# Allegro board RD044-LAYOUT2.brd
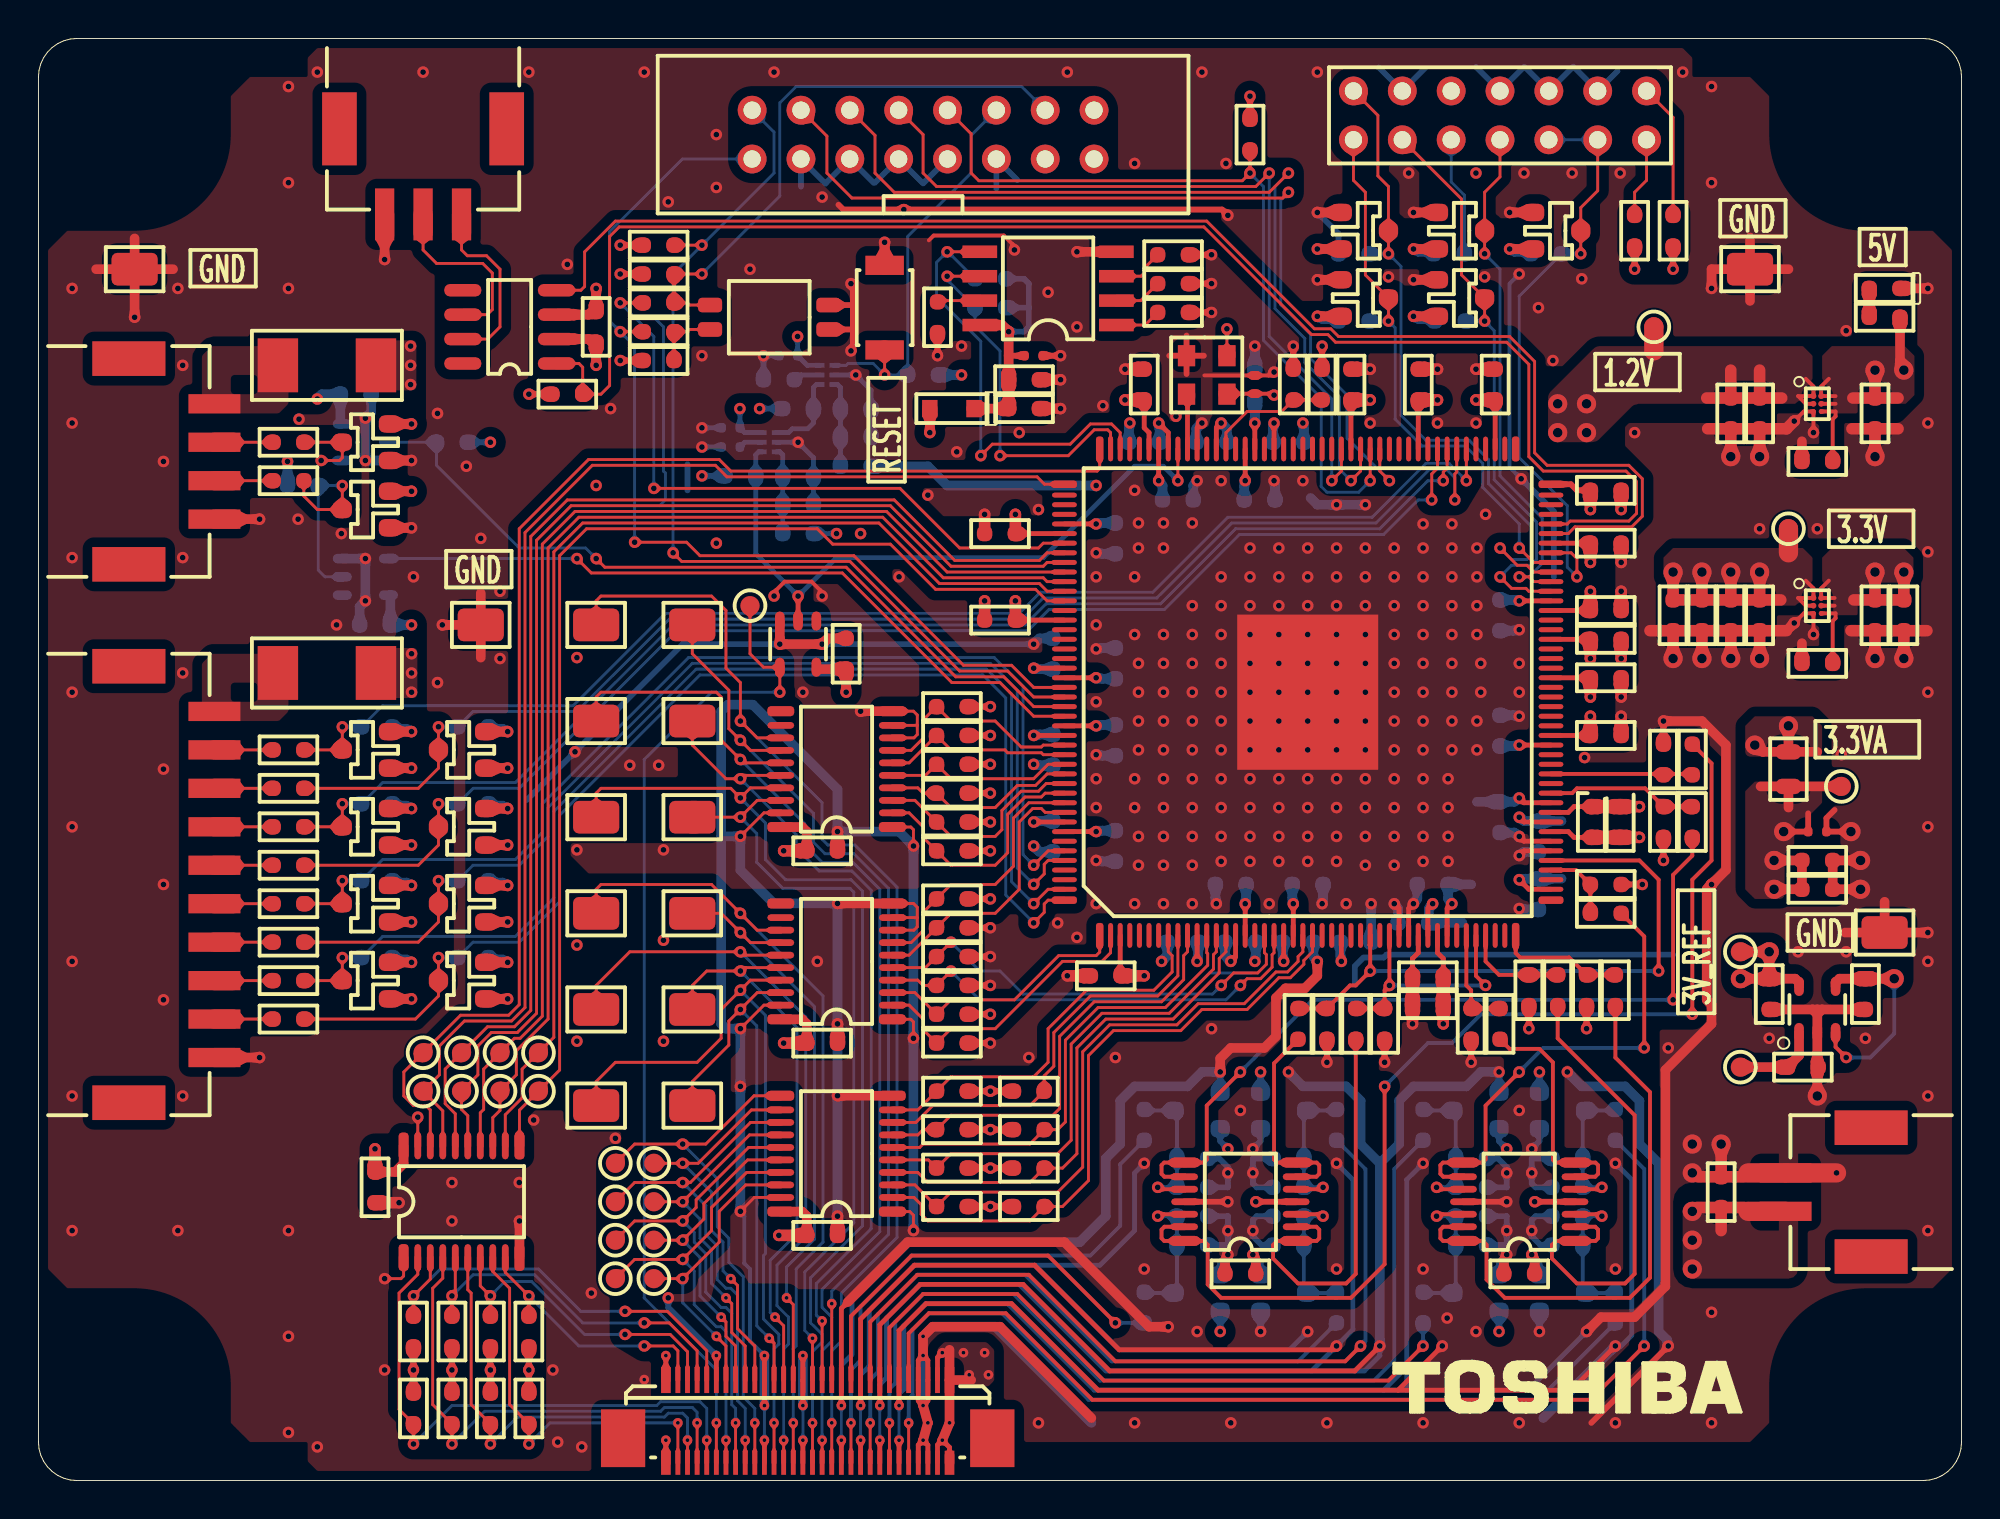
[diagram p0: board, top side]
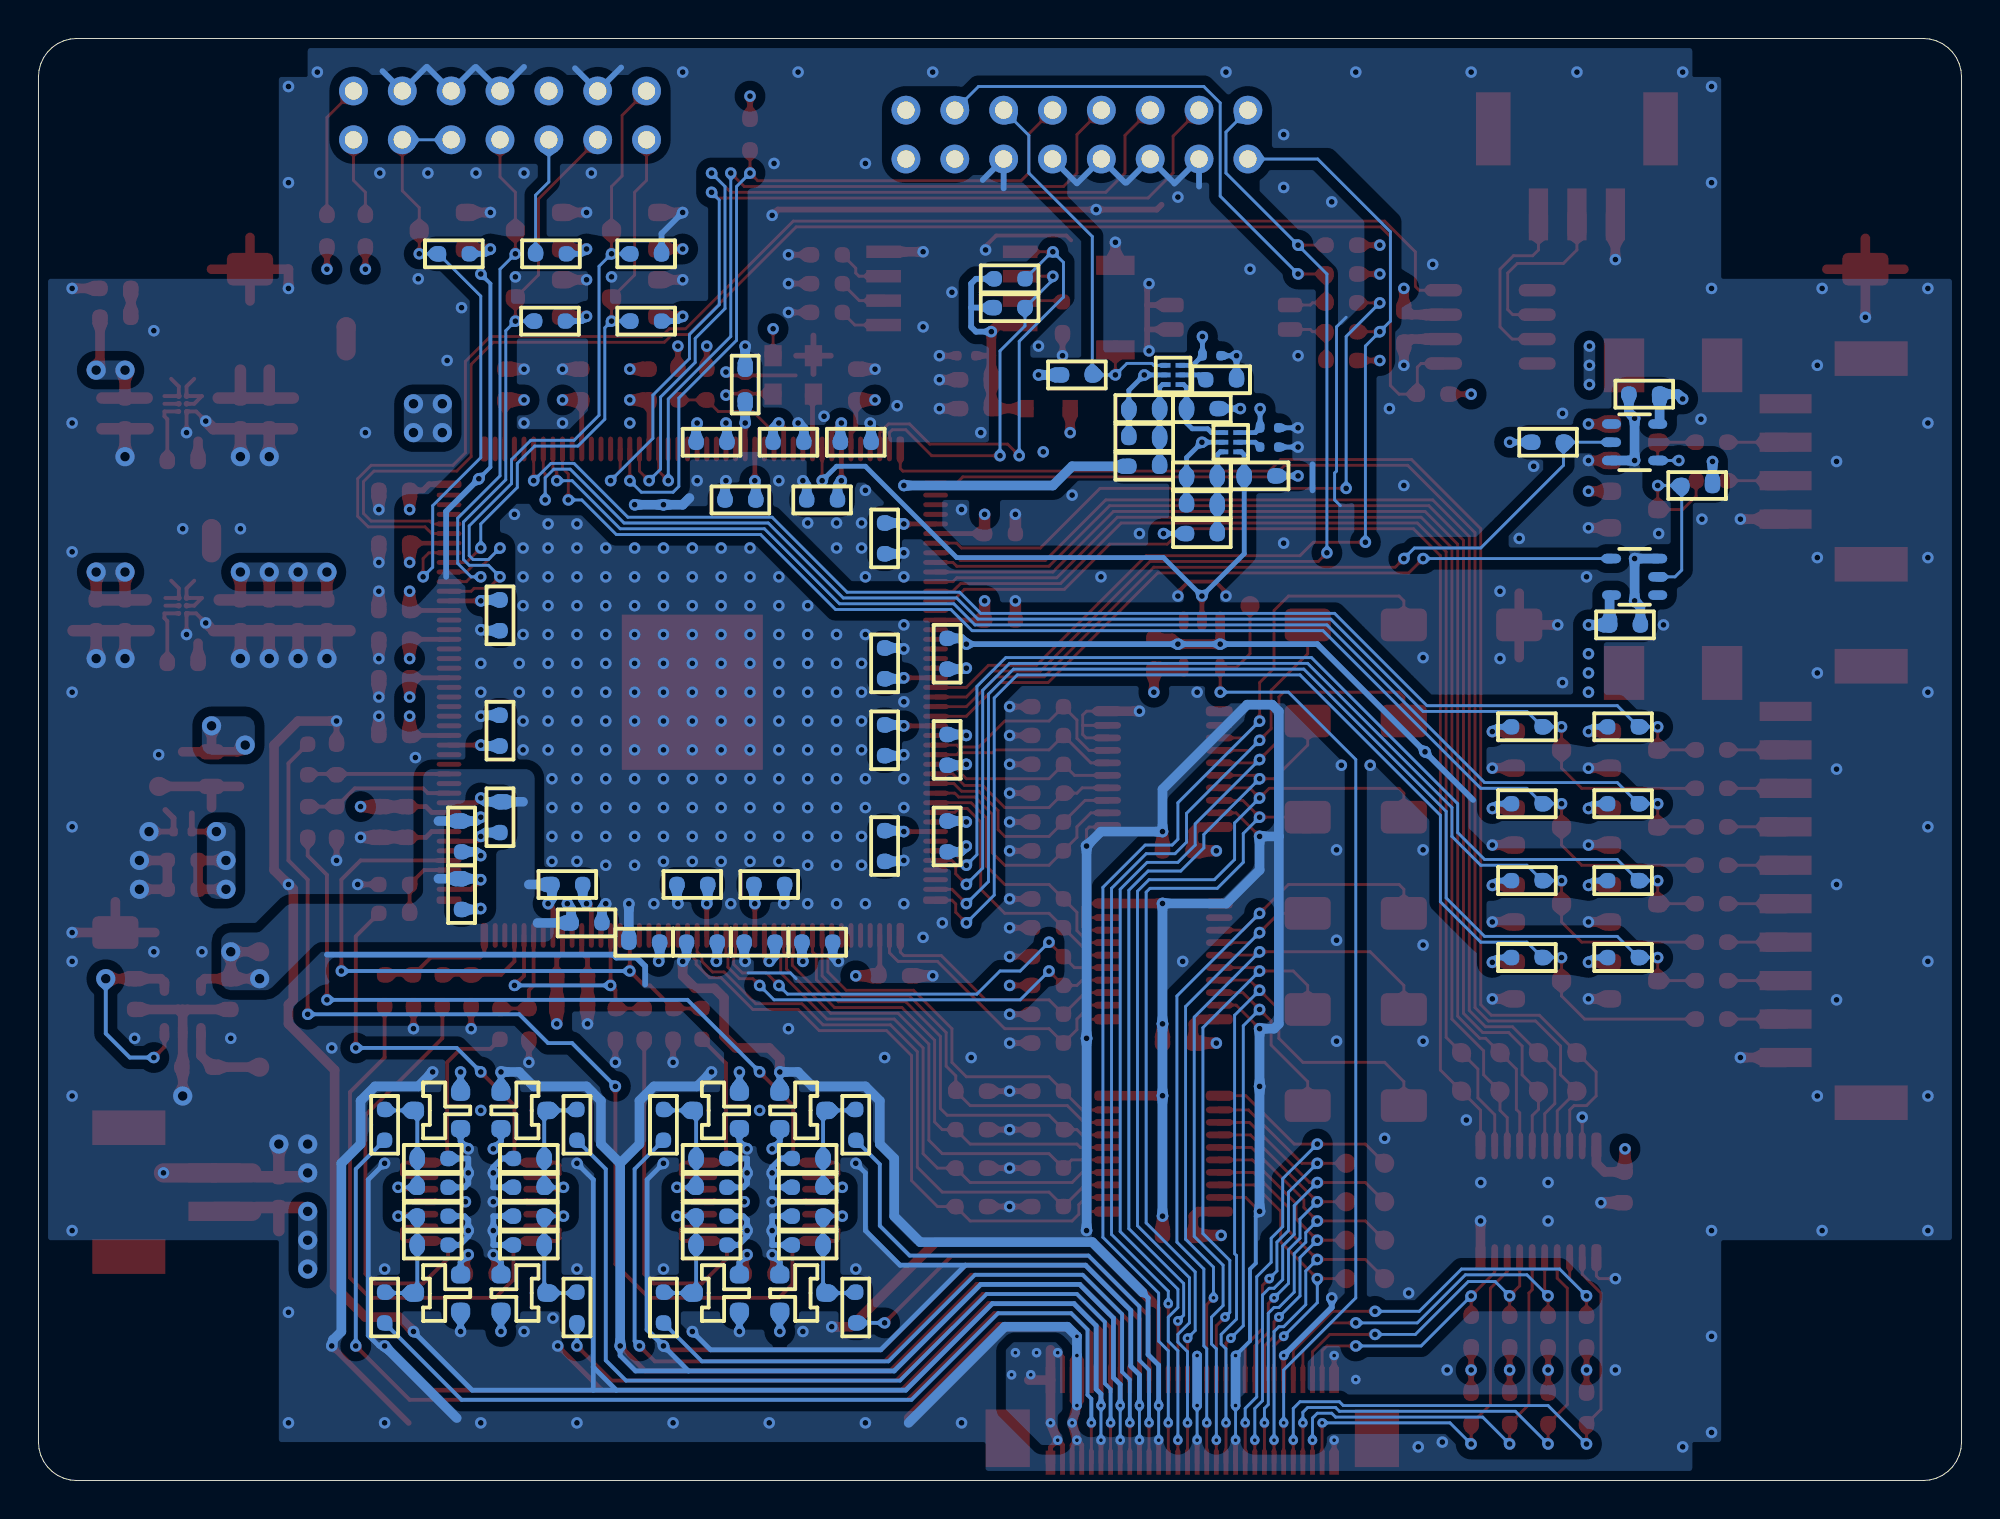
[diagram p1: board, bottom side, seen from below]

Outline 100 x 75 mm; copper layers: TOP, CONDUCTIVE2, CONDUCTIVE3, BOTTOM. Coordinates in mm from the lower left corner of the outline.
Outline path: 0,73 0.03,73.35 0.12,73.68 0.27,74 0.47,74.29 0.71,74.53 1,74.73 1.32,74.88 1.65,74.97 2,75 98,75 98.35,74.97 98.68,74.88 99,74.73 99.29,74.53 99.53,74.29 99.73,74 99.88,73.68 99.97,73.35 100,73 100,2 99.97,1.65 99.88,1.32 99.73,1 99.53,0.71 99.29,0.47 99,0.27 98.68,0.12 98.35,0.03 98,0 2,0 1.65,0.03 1.32,0.12 1,0.27 0.71,0.47 0.47,0.71 0.27,1 0.12,1.32 0.03,1.65 0,2 0,73

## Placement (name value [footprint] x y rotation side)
C1  -  [C_1005]  36 54.75 180 bottom
C2  -  [C_1608]  42.5 55.75 0 bottom
C3  -  [C_1608]  38.5 57.25 180 bottom
C4  -  [C_1608]  39.5 52.25 0 bottom
C5  -  [C_1005]  36 53.75 180 bottom
C6  -  [C_1005]  63.25 57 90 top
C7  -  [C_1005]  39 58.5 180 bottom
C8  -  [C_1608]  72.25 26.25 180 top
C9  -  [C_1608]  72.25 24.75 180 top
C10  -  [C_1608]  71.5 29 180 bottom
C11  -  [C_1608]  72.5 31 180 bottom
C12  -  [C_1608]  80.75 34.25 270 top
C13  -  [C_1608]  82.25 34.25 270 top
C14  -  [C_1608]  78 30.5 270 bottom
C15  -  [C_1608]  78 33.5 270 bottom
C16  -  [C_1608]  76 34.5 270 bottom
C17  -  [C_1005]  51.75 58.5 0 top
C18  -  [C_1608]  51.25 57.25 0 top
C19  -  [C_1608]  51.25 55.75 0 top
C20  -  [C_1608]  62 31 180 bottom
C21  -  [C_1608]  66 31 0 bottom
C22  -  [C_1608]  76 39 90 bottom
C23  -  [C_1608]  76 45 270 bottom
C24  -  [C_1608]  63.5 51 0 bottom
C25  -  [C_1608]  59.25 51 0 bottom
C26  -  [C_1608]  56 49 270 bottom
C27  -  [C_1608]  56 42.5 90 bottom
C28  -  [C_1608]  56 38.5 270 bottom
C29  -  [C_1608]  56 33 270 bottom
C30  -  [C_1608]  55.5 26.25 180 top
C31  -  [C_1608]  59.5 28 180 bottom
C32  -  [C_1608]  62.5 28 0 bottom
C33  -  [C_1608]  65.5 28 0 bottom
C34  -  [C_1608]  68.5 28 0 bottom
C35  -  [C_1608]  81.5 38.75 0 top
C36  -  [C_1608]  81.5 41.75 0 top
C37  -  [C_1608]  81.5 43.75 0 top
C38  -  [C_1608]  81.5 45.25 0 top
C39  -  [C_1608]  81.5 48.75 0 top
C40  -  [C_1608]  81.5 51.5 0 top
C41  -  [C_1608]  75.75 57 90 top
C42  -  [C_1608]  71.75 57 90 top
C43  -  [C_1608]  68.25 57 90 top
C44  -  [C_1608]  65 54 0 bottom
C45  -  [C_1608]  63.25 57 90 bottom
C46  -  [C_1608]  61 54 180 bottom
C47  -  [C_1608]  57.5 54 180 bottom
C48  -  [C_1608]  57.5 57 90 top
C49  -  [C_1608]  50 49.25 180 top
C50  -  [C_1608]  50 44.75 180 top
C51  -  [C_1608]  52.75 43 90 bottom
C52  -  [C_1608]  52.75 38 270 bottom
C53  -  [C_1608]  52.75 33.5 270 bottom
C54  -  [C_1608]  40.75 32.75 0 top
C55  -  [C_1608]  40.75 22.75 0 top
C56  -  [C_1608]  40.75 12.75 0 top
C57  -  [C_1608]  42 43 90 top
C58  -  [C_1608]  79.5 13.75 180 bottom
C59  -  [C_1608]  74.5 13.75 0 bottom
C60  -  [C_1608]  77 10.75 180 top
C61  -  [C_1608]  79.5 15.25 180 bottom
C62  -  [C_1608]  74.5 15.25 0 bottom
C63  -  [C_1608]  77.5 25.5 270 top
C64  -  [C_1608]  81.5 31 0 top
C65  -  [C_1608]  74.5 23.75 270 top
C66  -  [C_1608]  80.5 25.5 270 top
C67  -  [C_1608]  65 13.75 180 bottom
C68  -  [C_1608]  60 13.75 0 bottom
C69  -  [C_1608]  62.5 10.75 180 top
C70  -  [C_1608]  65 15.25 180 bottom
C71  -  [C_1608]  60 15.25 0 bottom
C72  -  [C_1608]  70 23.75 270 top
C73  -  [C_1608]  84.5 34.25 270 top
C74  -  [C_1608]  67 23.75 270 top
C75  -  [C_1608]  84.5 37.5 90 top
C76  -  [C_1608]  17.5 15.25 270 top
C77  -  [C_1608]  29 60 270 top
C78  -  [C_1608]  16.5 56.5 0 bottom
C79  -  [C_1608]  87.5 15 90 top
C80  -  [C_1608]  17.5 44.5 180 bottom
C81  -  [C_1608]  95.5 45 270 top
C82  -  [C_1608]  97 45 270 top
C83  -  [C_1005]  92.5 33.75 0 top
C84  -  [C_1608]  92.5 30.75 0 top
C85  -  [C_1608]  92.5 42.5 180 top
C86  -  [C_1608]  89.5 45 270 top
C87  -  [C_1608]  88 45 270 top
C88  -  [C_1608]  86.5 45 270 top
C89  -  [C_1608]  85 45 270 top
C90  -  [C_1608]  92.5 32.25 0 top
C91  -  [C_1608]  90 25.3 270 top
C92  -  [C_1608]  95.5 55.5 270 top
C93  -  [C_1608]  89.5 55.5 270 top
C94  -  [C_1608]  88 55.5 270 top
C95  -  [C_1608]  91.75 21.5 0 top
C96  -  [C_1608]  92.5 53 180 top
C97  -  [C_1608]  95 25.3 270 top
CN1  -  [CN_XG8W_1431]  76 71 0 top
CN2  -  [CN_XG4C_1631]  46 70 0 top
CN3  -  [CN_WR_60P_HF_HD_A1E]  40 3.05 0 top
CN4  -  [CN_SM03B_PASS_TBT]  20 70.85 0 top
CN5  -  [CN_SM02B_PASS_TBT]  95.85 15 270 top
CN6  -  [CN_SM04B_PASS_TBT]  4.15 53 90 top
CN7  -  [CN_SM10B_PASS_TBT]  4.15 31 90 top
D1  -  [D_SC_59_TO_236MOD_SO_1]  69 61.5 0 top
D2  -  [D_SC_59_TO_236MOD_SO_1]  69 65 0 top
D3  -  [D_SC_59_TO_236MOD_SO_1]  74 61.5 0 top
D4  -  [D_SC_59_TO_236MOD_SO_1]  74 65 0 top
D5  -  [D_SC_59_TO_236MOD_SO_1]  79 65 0 top
D6  -  [D_1_1E1A_USC_AK]  47.5 55.75 0 top
D7  -  [D_SC_59_TO_236MOD_SO_1]  79.25 9.75 0 bottom
D8  -  [D_SC_59_TO_236MOD_SO_1]  74.75 9.75 180 bottom
D9  -  [D_SC_59_TO_236MOD_SO_1]  79.25 19.25 0 bottom
D10  -  [D_SC_59_TO_236MOD_SO_1]  74.75 19.25 180 bottom
D11  -  [D_SC_59_TO_236MOD_SO_1]  64.75 9.75 0 bottom
D12  -  [D_SC_59_TO_236MOD_SO_1]  60.25 9.75 180 bottom
D13  -  [D_SC_59_TO_236MOD_SO_1]  64.75 19.25 0 bottom
D14  -  [D_SC_59_TO_236MOD_SO_1]  60.25 19.25 180 bottom
D15  -  [D_SC_59_TO_236MOD_SO_1]  17 54 180 top
D16  -  [D_SC_59_TO_236MOD_SO_1]  17 50.5 180 top
D17  -  [D_SC_59_TO_236MOD_SO_1]  17 38 180 top
D18  -  [D_SC_59_TO_236MOD_SO_1]  22 38 180 top
D19  -  [D_SC_59_TO_236MOD_SO_1]  17 34 180 top
D20  -  [D_SC_59_TO_236MOD_SO_1]  22 34 180 top
D21  -  [D_SC_59_TO_236MOD_SO_1]  17 30 180 top
D22  -  [D_SC_59_TO_236MOD_SO_1]  22 30 180 top
D23  -  [D_SC_59_TO_236MOD_SO_1]  17 26 180 top
D24  -  [D_SC_59_TO_236MOD_SO_1]  22 26 180 top
FU1  -  [F_CCF1N]  15 58 0 top
FU2  -  [F_CCF1N]  15 42 0 top
IC1  -  [IC_SON6_0_5_DRY_R_PU_1]  41 57.5 270 bottom
IC2  -  [IC_SON6_0_5_DRY_R_PU_1]  38 54 270 bottom
IC3  -  [IC_QFP176_0_5_S_PQFP_1]  66 41 0 top
IC4  -  [IC_SOP8_1_27_SM]  52.5 62 90 top
IC5  -  [IC_SOP20_0_65_TSSOP2_1]  41.5 37 90 top
IC6  -  [IC_SOP20_0_65_TSSOP2_1]  41.5 27 90 top
IC7  -  [IC_SOP20_0_65_TSSOP2_1]  41.5 17 90 top
IC8  -  [IC_SSOP5_P_0_95_TOSH_1]  39.5 43.5 90 top
IC9  -  [IC_SOP14_0_65_PW]  77 14.5 90 top
IC10  -  [IC_SOP14_0_65_PW]  62.5 14.5 90 top
IC11  -  [IC_SOP20_0_65_TSSOP2_1]  22 14.5 0 top
IC12  -  [IC_SOP8_1_27_D]  24.5 60 90 top
IC13  -  [IC_SSOP5_P_0_95_TOSH_1]  17 54 0 bottom
IC14  -  [IC_SSOP5_P_0_95_TOSH_1]  17 47 180 bottom
IC15  -  [IC_SOP5_0_95_DDC]  92.5 24.5 270 top
L1  -  [L_2012]  91 37 90 top
LED1  -  [LED_1608_AK]  96 62 0 top
NOREF  -  []  95 70 0 top
NOREF#2  -  []  5 70 0 top
NOREF#3  -  []  5 5 0 top
NOREF#4  -  []  70.5 3.5 0 top
NOREF#5  -  []  95 5 0 top
PAD1  -  [TP_PAD1_0]  32 10.5 0 top
PAD2  -  [TP_PAD1_0]  30 10.5 0 top
PAD3  -  [TP_PAD1_0]  32 12.5 0 top
PAD4  -  [TP_PAD1_0]  30 12.5 0 top
PAD5  -  [TP_PAD1_0]  32 14.5 0 top
PAD6  -  [TP_PAD1_0]  30 14.5 0 top
PAD7  -  [TP_PAD1_0]  32 16.5 0 top
PAD8  -  [TP_PAD1_0]  30 16.5 0 top
PAD9  -  [TP_PAD1_0]  37 45.5 0 top
PAD10  -  [TP_PAD1_0]  20 22.25 0 top
PAD11  -  [TP_PAD1_0]  20 20.25 0 top
PAD12  -  [TP_PAD1_0]  22 22.25 0 top
PAD13  -  [TP_PAD1_0]  22 20.25 0 top
PAD14  -  [TP_PAD1_0]  24 22.25 0 top
PAD15  -  [TP_PAD1_0]  24 20.25 0 top
PAD16  -  [TP_PAD1_0]  26 22.25 0 top
PAD17  -  [TP_PAD1_0]  26 20.25 0 top
PAD18  -  [TP_PAD1_0]  91 49.5 0 top
PAD19  -  [TP_PAD1_0]  93.75 36.1 0 top
PAD20  -  [TP_PAD1_0]  88.5 27.5 0 top
PAD21  -  [TP_PAD1_0]  84 60 0 top
PAD22  -  [TP_PAD1_0]  88.5 21.5 0 top
PS1  -  [BGA_6_0_4_WCSP6F]  92.5 45.5 0 top
PS2  -  [BGA_6_0_4_WCSP6F]  92.5 56 0 top
R1  -  [R_1608]  46 57.5 180 bottom
R2  -  [R_1608]  39.5 49.25 180 bottom
R3  -  [R_1608]  42.5 54.25 0 bottom
R4  -  [R_1608]  39.5 50.75 0 bottom
R5  -  [R_1608]  39.5 55.75 0 bottom
R6  -  [R_1608]  42.5 52.75 180 bottom
R7  -  [R_1608]  36.5 52.25 0 bottom
R8  -  [R_1608]  68.4 60.3 0 bottom
R9  -  [R_1608]  73.4 60.3 0 bottom
R10  -  [R_1608]  78.4 63.8 0 bottom
R11  -  [R_1608]  73.35 63.8 0 bottom
R12  -  [R_1608]  83 65 90 top
R13  -  [R_1608]  85 65 90 top
R14  -  [R_1608]  68.4 63.8 180 bottom
R15  -  [R_1608]  32.25 64.25 180 top
R16  -  [R_1608]  63 70 90 top
R17  -  [R_1608]  32.25 62.75 0 top
R18  -  [R_1608]  66.75 57 270 top
R19  -  [R_1608]  65.25 57 270 top
R20  -  [R_1608]  49.5 61 0 bottom
R21  -  [R_1608]  49.5 62.5 0 bottom
R22  -  [R_1608]  59 60.75 180 top
R23  -  [R_1608]  59 62.25 180 top
R24  -  [R_1608]  59 63.75 180 top
R25  -  [R_1608]  46.75 60.5 90 top
R26  -  [R_1608]  32.25 58.25 0 top
R28  -  [R_1608]  32.25 59.75 0 top
R29  -  [R_1608]  32.25 61.25 0 top
R30  -  [R_1608]  47.5 32.75 0 top
R31  -  [R_1608]  47.5 34.25 0 top
R32  -  [R_1608]  47.5 35.75 0 top
R33  -  [R_1608]  47.5 37.25 0 top
R34  -  [R_1608]  47.5 38.75 0 top
R35  -  [R_1608]  47.5 40.25 0 top
R36  -  [R_1608]  47.5 22.75 0 top
R37  -  [R_1608]  47.5 24.25 0 top
R38  -  [R_1608]  47.5 25.75 0 top
R39  -  [R_1608]  47.5 27.25 0 top
R40  -  [R_1608]  47.5 28.75 0 top
R41  -  [R_1608]  47.5 30.25 0 top
R42  -  [R_1608]  51.5 14.25 180 top
R43  -  [R_1608]  47.5 14.25 0 top
R44  -  [R_1608]  51.5 16.25 180 top
R45  -  [R_1608]  47.5 16.25 0 top
R46  -  [R_1608]  51.5 18.25 180 top
R47  -  [R_1608]  47.5 18.25 0 top
R48  -  [R_1608]  51.5 20.25 180 top
R49  -  [R_1608]  47.5 20.25 0 top
R50  -  [R_1608]  82 9 270 bottom
R51  -  [R_1608]  72 9 90 bottom
R52  -  [R_1608]  79.5 12.25 180 bottom
R53  -  [R_1608]  74.5 12.25 0 bottom
R54  -  [R_1608]  82 18.5 270 bottom
R55  -  [R_1608]  72 18.5 90 bottom
R56  -  [R_1608]  79.5 16.75 180 bottom
R57  -  [R_1608]  74.5 16.75 0 bottom
R58  -  [R_1608]  79 25.5 270 top
R59  -  [R_1608]  81.5 29.5 0 top
R60  -  [R_1608]  76 23.75 270 top
R61  -  [R_1608]  82 25.5 270 top
R62  -  [R_1608]  67.5 9 270 bottom
R63  -  [R_1608]  57.5 9 90 bottom
R64  -  [R_1608]  65 12.25 180 bottom
R65  -  [R_1608]  60 12.25 0 bottom
R66  -  [R_1608]  67.5 18.5 270 bottom
R67  -  [R_1608]  57.5 18.5 90 bottom
R68  -  [R_1608]  65 16.75 180 bottom
R69  -  [R_1608]  60 16.75 0 bottom
R70  -  [R_1608]  68.5 23.75 270 top
R71  -  [R_1608]  86 34.25 270 top
R72  -  [R_1608]  65.5 23.75 270 top
R73  -  [R_1608]  86 37.5 90 top
R74  -  [R_1608]  19.5 3.75 270 top
R75  -  [R_1608]  19.5 7.75 90 top
R76  -  [R_1608]  21.5 3.75 270 top
R77  -  [R_1608]  21.5 7.75 90 top
R78  -  [R_1608]  23.5 3.75 270 top
R79  -  [R_1608]  23.5 7.75 90 top
R80  -  [R_1608]  25.5 3.75 270 top
R81  -  [R_1608]  96 60.5 180 top
R82  -  [R_1608]  25.5 7.75 90 top
R83  -  [R_1608]  27.5 56.5 0 top
R84  -  [R_1608]  21.5 54 180 bottom
R85  -  [R_1608]  13 54 0 top
R86  -  [R_1608]  13.75 51.75 0 bottom
R87  -  [R_1608]  13 52 0 top
R88  -  [R_1608]  17.6 39.2 180 bottom
R89  -  [R_1608]  22.6 39.2 180 bottom
R90  -  [R_1608]  17.6 35.2 180 bottom
R91  -  [R_1608]  22.6 35.2 180 bottom
R92  -  [R_1608]  17.6 31.2 180 bottom
R93  -  [R_1608]  22.6 31.2 180 bottom
R94  -  [R_1608]  17.6 27.2 180 bottom
R95  -  [R_1608]  22.6 27.2 180 bottom
R96  -  [R_1608]  13 38 0 top
R97  -  [R_1608]  13 32 0 top
R98  -  [R_1608]  13 36 0 top
R99  -  [R_1608]  13 34 0 top
R100  -  [R_1608]  13 30 0 top
R101  -  [R_1608]  13 28 0 top
R102  -  [R_1608]  13 26 0 top
R103  -  [R_1608]  13 24 0 top
SW1  -  [SW_SKRKAEE010]  44 61 270 top
SW2  -  [SW_A6H_210X]  38 60.5 90 top
TP1  -  [TP_HK_3_G]  34 34.5 0 top
TP2  -  [TP_HK_3_G]  29 34.5 0 top
TP3  -  [TP_HK_3_G]  34 39.5 0 top
TP4  -  [TP_HK_3_G]  29 39.5 0 top
TP5  -  [TP_HK_3_G]  34 44.5 0 top
TP6  -  [TP_HK_3_G]  29 44.5 0 top
TP7  -  [TP_HK_3_G]  34 19.5 0 top
TP8  -  [TP_HK_3_G]  29 19.5 0 top
TP9  -  [TP_HK_3_G]  34 24.5 0 top
TP10  -  [TP_HK_3_G]  29 24.5 0 top
TP11  -  [TP_HK_3_G]  34 29.5 0 top
TP12  -  [TP_HK_3_G]  29 29.5 0 top
TP13  -  [TP_HK_3_G]  96 28.5 0 top
TP14  -  [TP_HK_3_G]  23 44.5 0 top
TP24  -  [TP_HK_3_G]  89 63 0 top
TP25  -  [TP_HK_3_G]  5 63 0 top
X1  -  [Y_ASEMB_DSC1001_3225_1]  60.75 57.5 180 top

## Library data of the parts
C1 C5-C7 C17 C83 = C-GRM155R70J104KA01D
C2 C4 = C-GRM188R71C102KA01D
C3 = C-1608_NM
C8-C16 C18 C20-C53 C85 C86 C89 C90 C96 C97 = C-GRM188R71A105KA61D
C19 C79 C81 C82 C84 C87 C88 C92-C94 = C-GRM188R61A106KE69D
C54-C57 C60 C69 C76-C78 C80 C91 C95 = C-GRM188R71H104KA93D
C58 C59 C61 C62 C67 C68 C70 C71 = C-GRM1885C1H471JA01D
C63-C66 C72-C75 = C-GRM188R11H153KA01D
CN1 = CN-XG8W-1431
CN2 = CN-XG4C-1631
CN3 = CN-WR-60P-HF-HD-A1E
CN4 = CN-SM03B-PASS-TBT_LF_SN
CN5 = CN-SM02B-PASS-TBT_LF_SN
CN6 = CN-SM04B-PASS-TBT_LF_SN
CN7 = CN-SM10B-PASS-TBT_LF_SN
D1-D5 D7-D24 = D-1SS396_AK
D6 = D-CUS05F30
FU1 FU2 = FU-CCF1N1.6TTE
IC1 IC2 = IC-TPS3897ADRY
IC3 = IC-TMS320F28377SPTP
IC4 = IC-24LC512-I_SM
IC5-IC7 = IC-74VHCT540AFT
IC8 IC13 IC14 = IC-TC7SH17F
IC9 IC10 = IC-OPA4322AIPWR
IC11 = IC-TC74VHC540FT
IC12 = IC-TCAN332D
IC15 = IC-REF2030AIDDCT
L1 = L-MMZ2012S601AT000
LED1 = LED-VCDG1111C-4BY3C-TR
PAD1-PAD22 = TP-PAD1.0
PS1 = PS-TCR15AG33
PS2 = PS-TCR15AG12
R1 R12 R13 R20 R21 = R-ERJ3EKF4701V
R2 = R-ERA3AEB304V
R3 R17 R22-R26 = R-ERJ3EKF1003V
R4 = R-ERA3AEB563V
R5 R7 R15 R16 R30-R51 R54 R55 R62 R63 R66 R67 R74-R80 R82-R84 R86 R88-R95 = R-ERJ3EKF1002V
R6 = R-ERA3AEB134V
R8-R10 R19 = R-1608_NM
R11 R85 R87 R96-R103 = R-ERJ3EKF1000V
R14 R28 R29 = R-ERJ3EKF2201V
R18 = R-RK73Z1JTTD
R52 R53 R56 R57 R64 R65 R68 R69 = R-ERJ3EKF1502V
R58-R61 R70-R73 = R-ERJ3EKF33R0V
R81 = R-ERJ3EKF4700V
SW1 = SW-SKRKAEE010
SW2 = SW-A6H-2102
TP1-TP14 TP24 TP25 = TP-HK-3-G
X1 = X-ASEMB-20.000MHZ-XY-T

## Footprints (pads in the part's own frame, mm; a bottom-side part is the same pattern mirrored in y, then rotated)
BGA_6_0_4_WCSP6F
  round 0.3 smd: A1(-0.2,0.4) A2(0.2,0.4) B1(-0.2,0) B2(0.2,0)
  round 0.25 smd: C1(-0.2,-0.4) C2(0.2,-0.4)
C_1005
  custom 0.113x0.113 smd: 1(-0.475,0) 2(0.475,0)
C_1608
  custom 0.2x0.2 smd: 1(-0.8,0) 2(0.8,0)
CN_SM02B_PASS_TBT
  rect 1x2.7 smd: 1(1,-5) 2(-1,-5)
  rect 1.8x3.8 smd: PAD1(3.35,-0.55) PAD2(-3.35,-0.55)
CN_SM03B_PASS_TBT
  rect 1x2.7 smd: 1(2,-5) 2(0,-5) 3(-2,-5)
  rect 1.8x3.8 smd: PAD1(4.35,-0.55) PAD2(-4.35,-0.55)
CN_SM04B_PASS_TBT
  rect 1x2.7 smd: 1(3,-5) 2(1,-5) 3(-1,-5) 4(-3,-5)
  rect 1.8x3.8 smd: PAD1(5.35,-0.55) PAD2(-5.35,-0.55)
CN_SM10B_PASS_TBT
  rect 1x2.7 smd: 1(9,-5) 2(7,-5) 3(5,-5) 4(3,-5) 5(1,-5) 6(-1,-5) 7(-3,-5) 8(-5,-5) 9(-7,-5) 10(-9,-5)
  rect 1.8x3.8 smd: PAD1(11.35,-0.55) PAD2(-11.35,-0.55)
CN_WR_60P_HF_HD_A1E
  rect 0.5x1.25 smd: 1(7.375,-2.125) 59(-7.375,-2.125)
  rect 0.5x1.35 smd: 2(7.375,2.175) 60(-7.375,2.175)
  rect 0.25x1.25 smd: 3(6.75,-2.125) 5(6.25,-2.125) 7(5.75,-2.125) 9(5.25,-2.125) 11(4.75,-2.125) 13(4.25,-2.125) 15(3.75,-2.125) 17(3.25,-2.125) 19(2.75,-2.125) 21(2.25,-2.125) 23(1.75,-2.125) 25(1.25,-2.125) 27(0.75,-2.125) 29(0.25,-2.125) 31(-0.25,-2.125) 33(-0.75,-2.125) 35(-1.25,-2.125) 37(-1.75,-2.125) 39(-2.25,-2.125) 41(-2.75,-2.125) 43(-3.25,-2.125) 45(-3.75,-2.125) 47(-4.25,-2.125) 49(-4.75,-2.125) 51(-5.25,-2.125) 53(-5.75,-2.125) 55(-6.25,-2.125) 57(-6.75,-2.125)
  rect 0.25x1.35 smd: 4(6.75,2.175) 6(6.25,2.175) 8(5.75,2.175) 10(5.25,2.175) 12(4.75,2.175) 14(4.25,2.175) 16(3.75,2.175) 18(3.25,2.175) 20(2.75,2.175) 22(2.25,2.175) 24(1.75,2.175) 26(1.25,2.175) 28(0.75,2.175) 30(0.25,2.175) 32(-0.25,2.175) 34(-0.75,2.175) 36(-1.25,2.175) 38(-1.75,2.175) 40(-2.25,2.175) 42(-2.75,2.175) 44(-3.25,2.175) 46(-3.75,2.175) 48(-4.25,2.175) 50(-4.75,2.175) 52(-5.25,2.175) 54(-5.75,2.175) 56(-6.25,2.175) 58(-6.75,2.175)
  rect 2.3x3 smd: NC1(-9.6,-0.85) NC2(9.6,-0.85)
CN_XG4C_1631
  round 1.5 hole 0.9: 1(-8.89,-1.27) 2(-8.89,1.27) 3(-6.35,-1.27) 4(-6.35,1.27) 5(-3.81,-1.27) 6(-3.81,1.27) 7(-1.27,-1.27) 8(-1.27,1.27) 9(1.27,-1.27) 10(1.27,1.27) 11(3.81,-1.27) 12(3.81,1.27) 13(6.35,-1.27) 14(6.35,1.27) 15(8.89,-1.27) 16(8.89,1.27)
CN_XG8W_1431
  round 1.5 hole 0.9: 1(-7.62,-1.27) 2(-7.62,1.27) 3(-5.08,-1.27) 4(-5.08,1.27) 5(-2.54,-1.27) 6(-2.54,1.27) 7(0,-1.27) 8(0,1.27) 9(2.54,-1.27) 10(2.54,1.27) 11(5.08,-1.27) 12(5.08,1.27) 13(7.62,-1.27) 14(7.62,1.27)
D_1_1E1A_USC_AK
  rect 0.8x0.9 smd: A(-1.15,0) K(1.15,0)
D_SC_59_TO_236MOD_SO_1
  custom 0.225x0.225 smd: A(-1.2,0.95) K(-1.2,-0.95) K/A(1.2,0)
F_CCF1N
  rect 2.1x2.8 smd: 1(-2.55,0) 2(2.55,0)
IC_QFP176_0_5_S_PQFP_1
  custom 0.098x0.098 smd: 1(-10.815,-12.65) 44(10.815,-12.65) 45(12.65,-10.815) 88(12.65,10.815) 89(10.815,12.65) 132(-10.815,12.65) 133(-12.65,10.815) 176(-12.65,-10.815)
  custom 0.065x0.065 smd: 2(-10.25,-12.65) 3(-9.75,-12.65) 4(-9.25,-12.65) 5(-8.75,-12.65) 6(-8.25,-12.65) 7(-7.75,-12.65) 8(-7.25,-12.65) 9(-6.75,-12.65) 10(-6.25,-12.65) 11(-5.75,-12.65) 12(-5.25,-12.65) 13(-4.75,-12.65) 14(-4.25,-12.65) 15(-3.75,-12.65) 16(-3.25,-12.65) 17(-2.75,-12.65) 18(-2.25,-12.65) 19(-1.75,-12.65) 20(-1.25,-12.65) 21(-0.75,-12.65) 22(-0.25,-12.65) 23(0.25,-12.65) 24(0.75,-12.65) 25(1.25,-12.65) 26(1.75,-12.65) 27(2.25,-12.65) 28(2.75,-12.65) 29(3.25,-12.65) 30(3.75,-12.65) 31(4.25,-12.65) 32(4.75,-12.65) 33(5.25,-12.65) 34(5.75,-12.65) 35(6.25,-12.65) 36(6.75,-12.65) 37(7.25,-12.65) 38(7.75,-12.65) 39(8.25,-12.65) 40(8.75,-12.65) 41(9.25,-12.65) 42(9.75,-12.65) 43(10.25,-12.65) 46(12.65,-10.25) 47(12.65,-9.75) 48(12.65,-9.25) 49(12.65,-8.75) 50(12.65,-8.25) 51(12.65,-7.75) 52(12.65,-7.25) 53(12.65,-6.75) 54(12.65,-6.25) 55(12.65,-5.75) 56(12.65,-5.25) 57(12.65,-4.75) 58(12.65,-4.25) 59(12.65,-3.75) 60(12.65,-3.25) 61(12.65,-2.75) 62(12.65,-2.25) 63(12.65,-1.75) 64(12.65,-1.25) 65(12.65,-0.75) 66(12.65,-0.25) 67(12.65,0.25) 68(12.65,0.75) 69(12.65,1.25) 70(12.65,1.75) 71(12.65,2.25) 72(12.65,2.75) 73(12.65,3.25) 74(12.65,3.75) 75(12.65,4.25) 76(12.65,4.75) 77(12.65,5.25) 78(12.65,5.75) 79(12.65,6.25) 80(12.65,6.75) 81(12.65,7.25) 82(12.65,7.75) 83(12.65,8.25) 84(12.65,8.75) 85(12.65,9.25) 86(12.65,9.75) 87(12.65,10.25) 90(10.25,12.65) 91(9.75,12.65) 92(9.25,12.65) 93(8.75,12.65) 94(8.25,12.65) 95(7.75,12.65) 96(7.25,12.65) 97(6.75,12.65) 98(6.25,12.65) 99(5.75,12.65) 100(5.25,12.65) 101(4.75,12.65) 102(4.25,12.65) 103(3.75,12.65) 104(3.25,12.65) 105(2.75,12.65) 106(2.25,12.65) 107(1.75,12.65) 108(1.25,12.65) 109(0.75,12.65) 110(0.25,12.65) 111(-0.25,12.65) 112(-0.75,12.65) 113(-1.25,12.65) 114(-1.75,12.65) 115(-2.25,12.65) 116(-2.75,12.65) 117(-3.25,12.65) 118(-3.75,12.65) 119(-4.25,12.65) 120(-4.75,12.65) 121(-5.25,12.65) 122(-5.75,12.65) 123(-6.25,12.65) 124(-6.75,12.65) 125(-7.25,12.65) 126(-7.75,12.65) 127(-8.25,12.65) 128(-8.75,12.65) 129(-9.25,12.65) 130(-9.75,12.65) 131(-10.25,12.65) 134(-12.65,10.25) 135(-12.65,9.75) 136(-12.65,9.25) 137(-12.65,8.75) 138(-12.65,8.25) 139(-12.65,7.75) 140(-12.65,7.25) 141(-12.65,6.75) 142(-12.65,6.25) 143(-12.65,5.75) 144(-12.65,5.25) 145(-12.65,4.75) 146(-12.65,4.25) 147(-12.65,3.75) 148(-12.65,3.25) 149(-12.65,2.75) 150(-12.65,2.25) 151(-12.65,1.75) 152(-12.65,1.25) 153(-12.65,0.75) 154(-12.65,0.25) 155(-12.65,-0.25) 156(-12.65,-0.75) 157(-12.65,-1.25) 158(-12.65,-1.75) 159(-12.65,-2.25) 160(-12.65,-2.75) 161(-12.65,-3.25) 162(-12.65,-3.75) 163(-12.65,-4.25) 164(-12.65,-4.75) 165(-12.65,-5.25) 166(-12.65,-5.75) 167(-12.65,-6.25) 168(-12.65,-6.75) 169(-12.65,-7.25) 170(-12.65,-7.75) 171(-12.65,-8.25) 172(-12.65,-8.75) 173(-12.65,-9.25) 174(-12.65,-9.75) 175(-12.65,-10.25)
  rect 7.33x8.07 smd: P1(0,0)
IC_SON6_0_5_DRY_R_PU_1
  rect 0.25x0.49 smd: 1(-0.5,-0.38) 2(0,-0.375) 3(0.5,-0.375) 4(0.5,0.375) 5(0,0.375) 6(-0.5,0.375)
IC_SOP5_0_95_DDC
  custom 0.125x0.125 smd: 1(1.2,-0.95) 2(1.2,0) 3(1.2,0.95) 4(-1.2,0.95) 5(-1.2,-0.95)
IC_SOP8_1_27_D
  custom 0.163x0.163 smd: 1(-1.905,-2.435) 2(-0.635,-2.435) 3(0.635,-2.435) 4(1.905,-2.435) 5(1.905,2.435) 6(0.635,2.435) 7(-0.635,2.435) 8(-1.905,2.435)
IC_SOP8_1_27_SM
  rect 0.65x1.8 smd: 1(-1.905,-3.55) 2(-0.635,-3.55) 3(0.635,-3.55) 4(1.905,-3.55) 5(1.905,3.55) 6(0.635,3.55) 7(-0.635,3.55) 8(-1.905,3.55)
IC_SOP14_0_65_PW
  custom 0.131x0.131 smd: 1(-2.038,-2.9) 7(2.038,-2.9) 8(2.038,2.9) 14(-2.038,2.9)
  custom 0.087x0.087 smd: 2(-1.3,-2.9) 3(-0.65,-2.9) 4(0,-2.9) 5(0.65,-2.9) 6(1.3,-2.9) 9(1.3,2.9) 10(0.65,2.9) 11(0,2.9) 12(-0.65,2.9) 13(-1.3,2.9)
IC_SOP20_0_65_TSSOP2_1
  custom 0.131x0.131 smd: 1(-3.013,-2.9) 10(3.013,-2.9) 11(3.013,2.9) 20(-3.013,2.9)
  custom 0.087x0.087 smd: 2(-2.275,-2.9) 3(-1.625,-2.9) 4(-0.975,-2.9) 5(-0.325,-2.9) 6(0.325,-2.9) 7(0.975,-2.9) 8(1.625,-2.9) 9(2.275,-2.9) 12(2.275,2.9) 13(1.625,2.9) 14(0.975,2.9) 15(0.325,2.9) 16(-0.325,2.9) 17(-0.975,2.9) 18(-1.625,2.9) 19(-2.275,2.9)
IC_SSOP5_P_0_95_TOSH_1
  custom 0.125x0.125 smd: 1(1.2,-0.95) 2(1.2,0) 3(1.2,0.95) 4(-1.2,0.95) 5(-1.2,-0.95)
L_2012
  custom 0.2x0.2 smd: 1(-0.9,0) 2(0.9,0)
LED_1608_AK
  custom 0.2x0.2 smd: A(-0.8,0) K(0.8,0)
R_1608
  custom 0.2x0.2 smd: 1(-0.8,0) 2(0.8,0)
SW_A6H_210X
  custom 0.19x0.19 smd: 1(-0.635,-3.075) 2(0.635,-3.075) 3(0.635,3.075) 4(-0.635,3.075)
SW_SKRKAEE010
  rect 1x2 smd: 1(-2.2,0) 2(2.2,0)
TP_HK_3_G
  custom 0.425x0.425 smd: 1(0,0)
TP_PAD1_0
  round 1 smd: 1(0,0)
Y_ASEMB_DSC1001_3225_1
  rect 0.9x1.1 smd: 1(-1.05,-1) 2(1.05,-1) 3(1.05,1) 4(-1.05,1)

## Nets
1.2V: C20.1(TP-1) C21.1(TP-1) C22.1(TP-1) C23.1(TP-1) C24.1(TP-1) C25.1(TP-1) C26.1(TP-1) C27.1(TP-1) C28.1(TP-1) C29.1(TP-1) C93.1(TP-1) C94.1(TP-1) IC3.16 IC3.21 IC3.61 IC3.76 IC3.117 IC3.126 IC3.137 IC3.153 IC3.158 IC3.169 PAD21.1 PS2.A1 PS2.B1 R6.1(TP-1)
3.3V: C1.1(TP-1) C6.1(TP-1) C7.1(TP-1) C30.1(TP-1) C31.1(TP-1) C32.1(TP-1) C33.1(TP-1) C34.1(TP-1) C35.1(TP-1) C36.1(TP-1) C37.1(TP-1) C38.1(TP-1) C39.1(TP-1) C40.1(TP-1) C41.1(TP-1) C42.1(TP-1) C43.1(TP-1) C44.1(TP-1) C45.1(TP-1) C46.1(TP-1) C47.1(TP-1) C48.1(TP-1) C49.1(TP-1) C50.1(TP-1) C51.1(TP-1) C52.1(TP-1) C53.1(TP-1) C60.1(TP-1) C69.1(TP-1) C76.1(TP-1) C77.1(TP-1) C80.1(TP-1) C86.1(TP-1) C87.1(TP-1) C88.1(TP-1) C89.1(TP-1) CN2.13 D1.K D2.K D3.K D4.K D5.K D6.A D7.K D8.K D9.K D10.K D11.K D12.K D13.K D14.K D17.K D18.K D19.K D20.K D21.K D22.K D23.K D24.K FU2.2(TP-1) IC1.6 IC2.6 IC3.3 IC3.11 IC3.15 IC3.20 IC3.26 IC3.62 IC3.68 IC3.72 IC3.75 IC3.82 IC3.88 IC3.91 IC3.99 IC3.106 IC3.114 IC3.116 IC3.120 IC3.125 IC3.127 IC3.138 IC3.147 IC3.152 IC3.159 IC3.168 IC9.4 IC10.4 IC11.20 IC12.3 IC14.5 L1.2(TP-1) PAD18.1 PS1.A1 PS1.B1 R1.1(TP-1) R2.1(TP-1) R5.1(TP-1) R7.1(TP-1) R8.1(TP-1) R9.1(TP-1) R10.1(TP-1) R11.1(TP-1) R12.1(TP-1) R13.1(TP-1) R15.2(TP-1) R16.2(TP-1) R17.1(TP-1) R18.1(TP-1) R26.1(TP-1) R83.1(TP-1) R84.1(TP-1) R88.1(TP-1) R89.1(TP-1) R90.1(TP-1) R91.1(TP-1) R92.1(TP-1) R93.1(TP-1) R94.1(TP-1) R95.1(TP-1) X1.1 X1.4
3.3VA: C8.1(TP-1) C9.1(TP-1) C12.1(TP-1) C13.1(TP-1) C83.1(TP-1) C84.1(TP-1) C90.1(TP-1) IC3.36 IC3.54 L1.1(TP-1) PAD19.1
3V_REF: C10.1(TP-1) C11.1(TP-1) C14.1(TP-1) C15.1(TP-1) C16.1(TP-1) C91.1(TP-1) IC3.35 IC3.37 IC3.46 IC3.53 IC3.55 IC15.5 PAD20.1
5V: C54.1(TP-1) C55.1(TP-1) C56.1(TP-1) C57.1(TP-1) C78.1(TP-1) C79.1(TP-1) C81.1(TP-1) C82.1(TP-1) C85.1(TP-1) C92.1(TP-1) C96.1(TP-1) C97.1(TP-1) CN3.1 CN3.2 CN3.3 CN3.4 CN5.1 D15.K D16.K FU1.2(TP-1) IC5.20 IC6.20 IC7.20 IC8.5 IC13.5 IC15.3 IC15.4 PS1.A2 PS1.B2 PS1.C2 PS2.A2 PS2.B2 PS2.C2 R74.1(TP-1) R75.1(TP-1) R76.1(TP-1) R77.1(TP-1) R78.1(TP-1) R79.1(TP-1) R80.1(TP-1) R81.1(TP-1) R82.1(TP-1) R86.1(TP-1)
GND: C1.2(TP-1) C2.2(TP-1) C3.2(TP-1) C4.2(TP-1) C5.2(TP-1) C6.2(TP-1) C7.2(TP-1) C8.2(TP-1) C9.2(TP-1) C10.2(TP-1) C11.2(TP-1) C12.2(TP-1) C13.2(TP-1) C14.2(TP-1) C15.2(TP-1) C16.2(TP-1) C17.2(TP-1) C18.2(TP-1) C19.2(TP-1) C20.2(TP-1) C21.2(TP-1) C22.2(TP-1) C23.2(TP-1) C24.2(TP-1) C25.2(TP-1) C26.2(TP-1) C27.2(TP-1) C28.2(TP-1) C29.2(TP-1) C30.2(TP-1) C31.2(TP-1) C32.2(TP-1) C33.2(TP-1) C34.2(TP-1) C35.2(TP-1) C36.2(TP-1) C37.2(TP-1) C38.2(TP-1) C39.2(TP-1) C40.2(TP-1) C41.2(TP-1) C42.2(TP-1) C43.2(TP-1) C44.2(TP-1) C45.2(TP-1) C46.2(TP-1) C47.2(TP-1) C48.2(TP-1) C49.2(TP-1) C50.2(TP-1) C51.2(TP-1) C52.2(TP-1) C53.2(TP-1) C54.2(TP-1) C55.2(TP-1) C56.2(TP-1) C57.2(TP-1) C58.2(TP-1) C59.2(TP-1) C60.2(TP-1) C61.2(TP-1) C62.2(TP-1) C63.2(TP-1) C64.2(TP-1) C65.2(TP-1) C66.2(TP-1) C67.2(TP-1) C68.2(TP-1) C69.2(TP-1) C70.2(TP-1) C71.2(TP-1) C72.2(TP-1) C73.2(TP-1) C74.2(TP-1) C75.2(TP-1) C76.2(TP-1) C77.2(TP-1) C78.2(TP-1) C79.2(TP-1) C80.2(TP-1) C81.2(TP-1) C82.2(TP-1) C83.2(TP-1) C84.2(TP-1) C85.2(TP-1) C86.2(TP-1) C87.2(TP-1) C88.2(TP-1) C89.2(TP-1) C90.2(TP-1) C91.2(TP-1) C92.2(TP-1) C93.2(TP-1) C94.2(TP-1) C95.2(TP-1) C96.2(TP-1) C97.2(TP-1) CN1.4 CN1.8 CN1.10 CN1.12 CN2.3 CN2.5 CN2.7 CN2.9 CN2.11 CN3.5 CN3.6 CN3.7 CN3.8 CN3.11 CN3.12 CN3.15 CN3.16 CN3.19 CN3.20 CN3.23 CN3.24 CN3.31 CN3.32 CN3.39 CN3.40 CN3.50 CN3.59 CN3.60 CN4.3 CN5.2 CN6.4 CN7.10 D1.A D2.A D3.A D4.A D5.A D7.A D8.A D9.A D10.A D11.A D12.A D13.A D14.A D15.A D16.A D17.A D18.A D19.A D20.A D21.A D22.A D23.A D24.A IC1.2 IC2.2 IC3.32 IC3.33 IC3.34 IC3.50 IC3.51 IC3.52 IC3.122 IC3.P1 IC4.4 IC5.1 IC5.8 IC5.9 IC5.10 IC5.19 IC6.1 IC6.8 IC6.9 IC6.10 IC6.19 IC7.1 IC7.10 IC7.19 IC8.3 IC9.11 IC10.11 IC11.1 IC11.10 IC11.19 IC12.2 IC13.3 IC14.3 IC15.2 LED1.K PS1.C1 PS2.C1 R3.2(TP-1) R4.2(TP-1) R14.2(TP-1) R19.1(TP-1) R22.1(TP-1) R23.1(TP-1) R24.1(TP-1) R25.1(TP-1) R30.2(TP-1) R31.2(TP-1) R32.2(TP-1) R33.2(TP-1) R34.2(TP-1) R35.2(TP-1) R36.2(TP-1) R37.2(TP-1) R38.2(TP-1) R39.2(TP-1) R40.2(TP-1) R41.2(TP-1) R42.2(TP-1) R43.2(TP-1) R44.2(TP-1) R45.2(TP-1) R46.2(TP-1) R47.2(TP-1) R48.2(TP-1) R49.2(TP-1) R52.2(TP-1) R53.2(TP-1) R56.2(TP-1) R57.2(TP-1) R64.2(TP-1) R65.2(TP-1) R68.2(TP-1) R69.2(TP-1) SW1.1(TP-1) SW2.1 SW2.2 TP13.1 TP14.1 TP24.1 TP25.1 X1.2
/DI0_BI: CN3.51 IC11.2 R74.2(TP-1)
/DI1_BI: CN3.52 IC11.3 R75.2(TP-1)
/DI2_BI: CN3.53 IC11.4 R76.2(TP-1)
/DI3_BI: CN3.54 IC11.5 R77.2(TP-1)
/DI4_BI: CN3.55 IC11.6 R78.2(TP-1)
/DI5_BI: CN3.56 IC11.7 R79.2(TP-1)
/DI6_BI: CN3.57 IC11.8 R80.2(TP-1)
/DI7_BI: CN3.58 IC11.9 R82.2(TP-1)
/DO0_BO: CN3.41 IC7.11 PAD8.1
/DO1_BO: CN3.42 IC7.12 PAD7.1
/DO2_BO: CN3.43 IC7.13 PAD6.1
/DO3_BO: CN3.44 IC7.14 PAD5.1
/DO4_BO: CN3.45 IC7.15 PAD4.1
/DO5_BO: CN3.46 IC7.16 PAD3.1
/DO6_BO: CN3.47 IC7.17 PAD2.1
/DO7_BO: CN3.48 IC7.18 PAD1.1
/PWM1A_BO: CN3.25 IC5.13 TP6.1
/PWM1B_BO: CN3.26 IC5.14 TP5.1
/PWM2A_BO: CN3.27 IC5.15 TP4.1
/PWM2B_BO: CN3.28 IC5.16 TP3.1
/PWM3A_BO: CN3.29 IC5.17 TP2.1
/PWM3B_BO: CN3.30 IC5.18 TP1.1
/PWM4A_BO: CN3.33 IC6.13 TP12.1
/PWM4B_BO: CN3.34 IC6.14 TP11.1
/PWM5A_BO: CN3.35 IC6.15 TP10.1
/PWM5B_BO: CN3.36 IC6.16 TP9.1
/PWM6A_BO: CN3.37 IC6.17 TP8.1
/PWM6B_BO: CN3.38 IC6.18 TP7.1
/RESET_BO: CN3.49 IC8.4 PAD9.1
/RESET_SIG: IC2.4 IC3.124 IC8.2 R7.2(TP-1)
AD0: CN3.9 R50.2(TP-1)
AD1: CN3.10 R54.2(TP-1)
AD2: CN3.13 R55.1(TP-1)
AD3: CN3.14 R51.1(TP-1)
AD4: CN3.17 R62.2(TP-1)
AD5: CN3.18 R66.2(TP-1)
AD6: CN3.21 R67.1(TP-1)
AD7: CN3.22 R63.1(TP-1)
ADC01_P_DSP41: C63.1(TP-1) IC3.41 R58.1(TP-1)
ADC02_P_DSP39: C65.1(TP-1) IC3.39 R60.1(TP-1)
ADC03_P_DSP48: C64.1(TP-1) IC3.48 R59.1(TP-1)
ADC04_P_DSP44: C66.1(TP-1) IC3.44 R61.1(TP-1)
ADC05_P_DSP31: C72.1(TP-1) IC3.31 IC3.40 R70.1(TP-1)
ADC06_P_DSP29: C74.1(TP-1) IC3.29 IC3.49 R72.1(TP-1)
ADC07_P_DSP56: C73.1(TP-1) IC3.56 R71.1(TP-1)
ADC08_P_DSP58: C75.1(TP-1) IC3.58 R73.1(TP-1)
BOOT1_DSP: CN2.14 R17.2(TP-1) R29.2(TP-1) SW2.3
BOOT1_DSP139: IC3.139 R29.1(TP-1)
CANRX_A_DSP83: IC3.83 IC12.4
CANTX_A_DSP84: IC3.84 IC12.1 R83.2(TP-1)
CLK_20MHZ: IC3.123 X1.3
DI0_DSP132: IC3.132 IC11.18 PAD10.1
DI1_DSP133: IC3.133 IC11.17 PAD11.1
DI2_DSP140: IC3.140 IC11.16 PAD12.1
DI3_DSP141: IC3.141 IC11.15 PAD13.1
DI4_DSP142: IC3.142 IC11.14 PAD14.1
DI5_DSP143: IC3.143 IC11.13 PAD15.1
DI6_DSP144: IC3.144 IC11.12 PAD16.1
DI7_DSP145: IC3.145 IC11.11 PAD17.1
DIO08_DSP94: D17.K/A IC3.94 R88.2(TP-1) R96.2(TP-1)
DIO09_DSP95: D18.K/A IC3.95 R89.2(TP-1) R98.2(TP-1)
DIO10_DSP96: D19.K/A IC3.96 R90.2(TP-1) R99.2(TP-1)
DIO11_DSP97: D20.K/A IC3.97 R91.2(TP-1) R97.2(TP-1)
DIO12_DSP171: D21.K/A IC3.171 R92.2(TP-1) R100.2(TP-1)
DIO13_DSP172: D22.K/A IC3.172 R93.2(TP-1) R101.2(TP-1)
DIO14_DSP175: D23.K/A IC3.175 R94.2(TP-1) R102.2(TP-1)
DIO15_DSP176: D24.K/A IC3.176 R95.2(TP-1) R103.2(TP-1)
DO0_DSP8: IC3.8 IC7.9 R49.1(TP-1)
DO1_DSP9: IC3.9 IC7.8 R48.1(TP-1)
DO2_DSP10: IC3.10 IC7.7 R47.1(TP-1)
DO3_DSP12: IC3.12 IC7.6 R46.1(TP-1)
DO4_DSP13: IC3.13 IC7.5 R45.1(TP-1)
DO5_DSP14: IC3.14 IC7.4 R44.1(TP-1)
DO6_DSP22: IC3.22 IC7.3 R43.1(TP-1)
DO7_DSP23: IC3.23 IC7.2 R42.1(TP-1)
HSDT_/RESET: CN2.12 IC1.1 R1.2(TP-1) SW1.2(TP-1)
PWM1A_DSP160: IC3.160 IC5.7 R35.1(TP-1)
PWM1B_DSP161: IC3.161 IC5.6 R34.1(TP-1)
PWM2A_DSP162: IC3.162 IC5.5 R33.1(TP-1)
PWM2B_DSP163: IC3.163 IC5.4 R32.1(TP-1)
PWM3A_DSP164: IC3.164 IC5.3 R31.1(TP-1)
PWM3B_DSP165: IC3.165 IC5.2 R30.1(TP-1)
PWM4A_DSP166: IC3.166 IC6.7 R41.1(TP-1)
PWM4B_DSP167: IC3.167 IC6.6 R40.1(TP-1)
PWM5A_DSP18: IC3.18 IC6.5 R39.1(TP-1)
PWM5B_DSP19: IC3.19 IC6.4 R38.1(TP-1)
PWM6A_DSP1: IC3.1 IC6.3 R37.1(TP-1)
PWM6B_DSP2: IC3.2 IC6.2 R36.1(TP-1)
SCIRX_B_DSP157: IC3.157 IC14.4
SCIRXDA_DSP155: CN2.2 IC3.155 R15.1(TP-1)
SCITX_B_DSP156: IC3.156 IC13.2 R84.2(TP-1)
SCITXDA_DSP154: CN2.1 IC3.154 R28.1(TP-1)
SCL_A_DSP131: IC3.131 IC4.6 R20.1(TP-1)
SDA_A_DSP130: IC3.130 IC4.5 R21.1(TP-1)
SPISTEA_DSP107: CN2.8 IC3.107
SSCK_DSP105: CN2.6 IC3.105
SSI_DSP104: CN2.10 IC3.104 R16.1(TP-1)
SSO_DSP103: CN2.4 IC3.103
TCK_DSP81: CN1.9 CN1.11 D5.K/A IC3.81 R10.2(TP-1)
TDI_DSP77: CN1.3 D3.K/A IC3.77 R9.2(TP-1)
TDO_DSP78: CN1.7 D4.K/A IC3.78
TMS_DSP80: CN1.1 D1.K/A IC3.80 R8.2(TP-1)
TRST_DSP79: CN1.2 D2.K/A IC3.79 R14.1(TP-1)
N16607086: IC1.4 IC2.1 R5.2(TP-1)
N16607090: C4.1(TP-1) IC2.3 R2.2(TP-1) R4.1(TP-1)
N16607182: C2.1(TP-1) IC1.3 R3.1(TP-1) R6.2(TP-1)
N16607194: C3.1(TP-1) IC1.5
N16607210: C5.1(TP-1) IC2.5
N16608626: CN1.5 R11.2(TP-1)
N16609034: CN1.13 R12.2(TP-1)
N16609038: CN1.14 R13.2(TP-1)
N16609736: IC3.119 R18.2(TP-1) R19.2(TP-1)
N16610346: C17.1(TP-1) C18.1(TP-1) C19.1(TP-1) D6.K IC4.8 R20.2(TP-1) R21.2(TP-1)
N16610376: IC4.1 R22.2(TP-1)
N16610420: IC4.2 R23.2(TP-1)
N16610428: IC4.7 R25.2(TP-1)
N16610486: IC4.3 R24.2(TP-1)
N16610930: R26.2(TP-1) R28.2(TP-1) SW2.4
N16624647: C59.1(TP-1) D8.K/A IC9.12 R51.2(TP-1) R53.1(TP-1)
N16624651: C58.1(TP-1) D7.K/A IC9.3 R50.1(TP-1) R52.1(TP-1)
N16624783: IC9.1 IC9.2 R58.2(TP-1)
N16624799: IC9.13 IC9.14 R61.2(TP-1)
N16625013: C61.1(TP-1) D9.K/A IC9.5 R54.1(TP-1) R56.1(TP-1)
N16625021: C62.1(TP-1) D10.K/A IC9.10 R55.2(TP-1) R57.1(TP-1)
N16625097: IC9.6 IC9.7 R60.2(TP-1)
N16625113: IC9.8 IC9.9 R59.2(TP-1)
N16625873: C67.1(TP-1) D11.K/A IC10.3 R62.1(TP-1) R64.1(TP-1)
N16626013: IC10.1 IC10.2 R70.2(TP-1)
N16626029: IC10.13 IC10.14 R73.2(TP-1)
N16626045: C68.1(TP-1) D12.K/A IC10.12 R63.2(TP-1) R65.1(TP-1)
N16626273: C70.1(TP-1) D13.K/A IC10.5 R66.1(TP-1) R68.1(TP-1)
N16626281: C71.1(TP-1) D14.K/A IC10.10 R67.2(TP-1) R69.1(TP-1)
N16626357: IC10.6 IC10.7 R72.2(TP-1)
N16626365: IC10.8 IC10.9 R71.2(TP-1)
N16642513: C95.1(TP-1) IC15.1 PAD22.1
N16664780: D15.K/A IC13.4 R85.2(TP-1)
N16668564: D16.K/A IC14.2 R86.2(TP-1) R87.2(TP-1)
N16668568: CN6.3 R87.1(TP-1)
N16669496: CN4.1 IC12.7
N16669500: CN4.2 IC12.6
N16671270: CN6.2 R85.1(TP-1)
N16690596: LED1.A R81.2(TP-1)
N16817849: CN7.9 R103.1(TP-1)
N16817854: CN7.8 R102.1(TP-1)
N16817859: CN7.7 R101.1(TP-1)
N16817864: CN7.6 R100.1(TP-1)
N16817869: CN7.5 R97.1(TP-1)
N16817874: CN7.4 R99.1(TP-1)
N16817879: CN7.3 R98.1(TP-1)
N16817884: CN7.2 R96.1(TP-1)
N16840741: CN7.1 FU2.1(TP-1)
N16841842: CN6.1 FU1.1(TP-1)

Pads without a net: CN1 6; CN2 15 16; CN3 NC1 NC2; CN4 PAD1 PAD2; CN5 PAD1 PAD2; CN6 PAD1 PAD2; CN7 PAD1 PAD2; IC3 4 5 6 7 17 24 25 27 28 30 38 42 43 45 47 57 59 60 63 64 65 66 67 69 70 71 73 74 85 86 87 89 90 92 93 98 100 101 102 108 109 110 111 112 113 115 118 121 128 129 134 135 136 146 148 149 150 151 170 173 174; IC5 11 12; IC6 11 12; IC8 1; IC12 5 8; IC13 1; IC14 1

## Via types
v1: diameter 0.6, hole 0.3, TOP to BOTTOM, 709 vias
v2: diameter 1, hole 0.5, TOP to BOTTOM, 39 vias
v3: diameter 0.5, hole 0.2, TOP to BOTTOM, 59 vias

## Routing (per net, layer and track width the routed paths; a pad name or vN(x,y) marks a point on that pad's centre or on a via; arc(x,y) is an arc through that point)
1.2V: length 49.6
  TOP w0.2: 91.9,57.3 92.3,56.9 PS2.A1 91.5,56.4 91.9,56 PS2.B1
  TOP w0.25: IC3.16 v1(62.75,30) ; IC3.153 v1(55,41.75) ; IC3.21 v1(65.25,30) ; IC3.137 v1(55,49.75) ; IC3.158 v1(55,39.25) ; IC3.76 v1(77,45.75) ; IC3.117 v1(62.75,52) ; IC3.61 v1(77,38.25) ; IC3.126 v1(58.25,52) ; IC3.169 v1(55,33.75)
  TOP w0.6: C93.1 89.5,57.75 ; C93.1 90.65,56.3 ; C93.1 C94.1 ; C94.1 86.75,56.3 ; C94.1 88,57.75
  TOP w1: PAD21.1 84,58.75
  BOTTOM w0.5: v1(58.25,52) 58.45,51.74 C25.1 ; v1(55,41.75) 55.33,41.7 55.97,41.7 ; v1(55,39.25) 55.33,39.3 55.97,39.3 ; 43.56,52.75 46.25,52.75 47.25,51.75 v1(55,51.75) ; v1(55,49.75) 55.33,49.8 55.97,49.8 ; 76.03,45.8 76.67,45.8 v1(77,45.75) ; v1(55,33.75) 55.33,33.8 55.97,33.8 ; v1(62.75,30) 62.8,30.33 62.8,30.96 ; 62.7,51.03 62.7,51.67 v1(62.75,52) ; v1(77,38.25) 76.67,38.2 76.03,38.2 ; v1(65.25,30) 65.2,30.33 65.2,30.96
  BOTTOM w0.8: C21.1 65.2,30.96 ; C22.1 76.03,38.2 ; C26.1 55.97,49.8 ; C24.1 62.7,51.03 ; C27.1 55.97,41.7 ; C20.1 62.8,30.96 ; C28.1 55.97,39.3 ; C29.1 55.97,33.8 ; C23.1 76.03,45.8 ; R6.1 43.56,52.75
  vias: v2(79,56) v2(79,54.5) v2(80.5,56) v2(80.5,54.5)
3.3V: length 170.9
  TOP w0.15: 61.8,58.61 v1(61.8,59.9)
  TOP w0.2: v1(64.25,56.45) 63.93,56.52 63.36,56.52 ; 91.9,46.8 92.3,46.4 PS1.A1 91.5,45.9 91.9,45.5 PS1.B1 ; 63.14,56.52 61.93,56.52
  TOP w0.25: IC3.20 v1(64.75,27) ; v1(61.5,55) 61.25,54.75 IC3.120 ; IC3.127 57.75,54.5 57.5,54.75 57.5,56.05 ; IC3.168 v1(51.75,34.25) ; 80.55,41.75 IC3.68 ; IC3.138 50.95,49.25 ; IC3.125 58.75,54.5 v1(58.25,55) ; IC3.11 v1(60.25,27) ; IC3.26 v1(67.75,27) ; IC3.147 50.95,44.75 ; 80.55,38.75 IC3.62 ; IC3.159 v1(51.75,38.75) ; 80.55,48.75 IC3.82 ; IC3.99 71.75,56.05 ; IC3.91 75.75,56.05 ; IC3.106 68.25,56.05 ; v1(62,27) 62.25,27.25 IC3.15 ; IC3.114 v1(64.25,55) ; IC3.152 v1(51.75,42.25) ; 80.55,43.75 IC3.72 ; 80.55,45.25 IC3.75 ; IC3.116 v1(63.25,55) ; 56.25,26.4 IC3.3
  TOP w0.3: C40.1 80,51.5 79.69,51.81 79.26,51.81 ; 31.28,58.25 v1(30.25,58.25) ; 66.75,57.97 v1(66.75,59) ; 79.38,14.5 v1(77.8,14.5) ; 26.53,56.5 v1(25.5,56.5) ; 83,64.03 v1(83,63) ; 64.88,14.5 v1(63.3,14.5) ; 31.28,62.75 v1(30.25,62.75) ; 85,64.03 v1(85,63) ; 63,70.97 v1(63,72) ; 31.28,64.25 v1(30.25,64.25)
  TOP w0.35: 79.26,51.81 IC3.88 ; IC10.4 64.88,14.5 ; IC9.4 79.38,14.5
  TOP w0.45: 63.14,56.52 C6.1 63.36,56.52
  TOP w0.5: L1.2 92.5,37.9 ; L1.2 89.67,37.9 v2(89.25,38.25) ; L1.2 v2(91,39.25) ; 67.53,64.05 v1(66.5,64.05) ; IC11.20 18.99,16.49 18.55,16.05 17.59,16.05 ; 18.47,38.95 v1(19.4,38.95) ; v1(77.65,11.75) 77.8,11.46 C60.1 ; 23.47,30.95 v1(24.4,30.95) ; 18.47,34.95 v1(19.4,34.95) ; 29,61.06 v1(29,62) ; 72.53,60.55 v1(71.5,60.55) ; 23.47,26.95 v1(24.4,26.95) ; 18.47,26.95 v1(19.4,26.95) ; 77.53,64.05 v1(76.5,64.05) ; 23.47,34.95 v1(24.4,34.95) ; 46.35,55.49 v1(46.35,54.5) ; 72.53,64.05 v1(71.5,64.05) ; 27.83,60.63 28.59,60.63 C77.1 ; v1(63.15,11.75) 63.3,11.46 C69.1 ; 18.47,30.95 v1(19.4,30.95) ; 67.53,60.55 v1(66.5,60.55) ; 23.47,38.95 v1(24.4,38.95)
  TOP w0.6: 68.56,56.2 v1(69.25,56.2) ; 27.83,60.63 IC12.3 ; C86.1 v2(89.5,47.25) ; C86.1 C87.1 ; C86.1 90.6,45.8 ; C49.1 v1(50.8,50.25) ; 80.7,41.44 v1(80.7,40.75) ; 80.7,43.44 v1(80.7,42.75) ; v2(85,47.25) C89.1 C88.1 ; 80.7,48.44 v1(80.7,47.75) ; C87.1 C88.1 ; C87.1 v2(88,47.25) ; C88.1 v2(86.5,47.25) ; C50.1 v1(50.8,45.75) ; 80.7,51.19 v1(80.7,50.5) ; 75.44,56.2 v1(74.75,56.2) ; 80.7,45.56 v1(80.7,46.25) ; 17.5,16.36 v1(17.5,17.25) ; 72.06,56.2 v1(72.75,56.2) ; 56.61,26.25 v1(57.5,26.25) ; 57.19,56.2 v1(56.5,56.2) ; 80.7,39.06 v1(80.7,39.75)
  TOP w0.7: 56.25,26.25 56.25,26.4
  TOP w0.8: 68.56,56.2 C43.1 68.25,56.05 ; 57.19,56.2 C48.1 57.5,56.05 ; 71.75,56.05 C42.1 72.06,56.2 ; D6.A 46.35,55.49 ; 50.95,49.25 C49.1 ; R13.1 85,64.03 ; 75.44,56.2 C41.1 75.75,56.05 ; 17.59,16.05 C76.1 17.5,16.36 ; R17.1 31.28,62.75 ; R15.2 31.28,64.25 ; R16.2 63,70.97 ; R26.1 31.28,58.25 ; 80.7,48.44 C39.1 80.55,48.75 ; R83.1 26.53,56.5 ; 80.7,41.44 C36.1 80.55,41.75 ; 80.55,38.75 C35.1 80.7,39.06 ; 80.7,45.56 C38.1 80.55,45.25 ; 50.95,44.75 C50.1 ; 80.55,43.75 C37.1 80.7,43.44 ; C30.1 56.61,26.25 ; R12.1 83,64.03 ; R18.1 66.75,57.97 ; C77.1 29,61.06 ; C40.1 80.7,51.19
  TOP w0.9: D5.K 77.53,64.05 ; D18.K 23.47,38.95 ; D4.K 72.53,64.05 ; D20.K 23.47,34.95 ; D21.K 18.47,30.95 ; X1.1 61.8,58.61 ; D2.K 67.53,64.05 ; D22.K 23.47,30.95 ; D19.K 18.47,34.95 ; D1.K 67.53,60.55 ; D17.K 18.47,38.95 ; 61.93,56.52 61.8,56.52 ; D3.K 72.53,60.55 ; D24.K 23.47,26.95 ; D23.K 18.47,26.95
  TOP w1: PAD18.1 91,48.25
  BOTTOM w0.25: 40.45,49.25 v1(41.5,49.25) ; C7.1 39.98,58 IC1.6 ; IC2.6 36.73,54.5 C1.1 ; 39.48,58.63 v1(39.48,59.5) ; 36.48,54.88 v1(36.48,55.75)
  BOTTOM w0.3: v1(66.5,60.55) 66.75,60.3 R8.1 ; 22.47,54 v1(23.5,54) ; v1(24.4,30.95) 24.15,31.2 R93.1 ; v1(61.85,17.25) 61.45,17.65 D14.K ; R10.1 76.75,63.8 v1(76.5,64.05) ; R88.1 19.15,39.2 v1(19.4,38.95) ; v1(19.4,30.95) 19.15,31.2 R92.1 ; R9.1 71.75,60.3 v1(71.5,60.55) ; R91.1 24.15,35.2 v1(24.4,34.95) ; R90.1 19.15,35.2 v1(19.4,34.95) ; v1(77.65,11.75) 78.05,11.35 D7.K ; R94.1 19.15,27.2 v1(19.4,26.95) ; v1(76.35,17.25) 75.95,17.65 D10.K ; 38.53,55.75 v1(37.5,55.75) ; 78.05,20.38 v1(78.05,21.25) ; v1(24.4,26.95) 24.15,27.2 R95.1 ; v1(63.15,11.75) 63.55,11.35 D11.K ; 61.45,8.62 v1(61.45,7.75) ; 35.53,52.25 v1(34.5,52.25) ; 63.55,20.38 v1(63.55,21.25) ; 75.95,8.62 v1(75.95,7.75) ; R89.1 24.15,39.2 v1(24.4,38.95) ; R11.1 71.75,63.8 v1(71.5,64.05)
  BOTTOM w0.45: C1.1 36.48,54.88 ; C7.1 39.48,58.63
  BOTTOM w0.5: v1(51.75,42.25) 52.08,42.2 52.72,42.2 ; v1(51.75,38.75) 52.08,38.8 52.72,38.8 ; v1(58.25,55) 58.3,54.67 58.3,54.03 ; C32.1 61.7,27.3 v1(62,27) ; 52.72,34.3 52.08,34.3 v1(51.75,34.25) ; v1(67.75,27) 67.7,27.33 67.7,27.96 ; 63.25,55.94 v1(63.25,55) ; 64.7,27.96 64.7,27.33 v1(64.75,27) ; 60.3,27.96 60.3,27.33 v1(60.25,27) ; 64.2,54.03 64.2,54.67 v1(64.25,55) ; v1(61.5,55) 61.8,54.7 C46.1 ; 47.06,57.5 v1(48,57.5) ; 18.3,44.76 18.3,46.05 ; 18.56,44.5 v1(19.4,44.5)
  BOTTOM w0.8: C31.1 60.3,27.96 ; R84.1 22.47,54 ; 18.56,44.5 C80.1 18.3,44.76 ; C52.1 52.72,38.8 ; R5.1 38.53,55.75 ; C34.1 67.7,27.96 ; C33.1 64.7,27.96 ; C47.1 58.3,54.03 ; R2.1 40.45,49.25 ; R1.1 47.06,57.5 ; C53.1 52.72,34.3 ; C44.1 64.2,54.03 ; C45.1 63.25,55.94 ; R7.1 35.53,52.25 ; C51.1 52.72,42.2
  BOTTOM w0.9: D13.K 63.55,20.38 ; D9.K 78.05,20.38 ; D12.K 61.45,8.62 ; D8.K 75.95,8.62
  vias: v1(19.4,43) v1(19.4,42) v1(19.4,41)
3.3VA: length 21.4
  TOP w0.25: 73.05,26.26 73.05,27.15 72.75,27.45 IC3.36 ; IC3.54 79.55,34.75 79.85,35.05 80.74,35.05
  TOP w0.3: 92.03,34.7 C83.1 v2(90.75,33.75)
  TOP w0.5: v2(90.25,30.75) C84.1 C90.1 v2(90.25,32.25) ; L1.1 89.55,36.1 ; L1.1 91,35 ; L1.1 PAD19.1
  TOP w0.6: 73.05,25.94 73.05,25.06 ; 73.05,24.44 v1(73.05,23.75) ; 81.06,35.05 81.94,35.05 ; 82.56,35.05 v1(83.25,35.05)
  TOP w0.8: 81.94,35.05 C13.1 82.56,35.05 ; 73.05,26.26 C8.1 73.05,25.94 ; 81.06,35.05 C12.1 80.74,35.05 ; 73.05,24.44 C9.1 73.05,25.06
3V_REF: length 26.9
  TOP w0.25: v1(73.5,30) 73.25,29.75 IC3.37 ; IC3.46 77.5,30.75 v1(77,31.25) ; IC3.55 77.25,35.25 v1(77,35.5) ; IC3.53 77.25,34.25 v1(77,34.5) ; v1(72.5,30) 72.25,29.75 IC3.35
  TOP w0.5: 89.74,26.1 v2(88.5,26.1) ; PAD20.1 v2(90,27.5) 90,26.36 ; IC15.5 91.55,25.9 91.35,26.1 90.23,26.1
  TOP w0.8: C91.1 89.74,26.1 ; C91.1 90,26.36 ; C91.1 90.23,26.1
  BOTTOM w0.5: v1(72.5,30) 72.3,29.74 C10.1 ; 78.26,31.3 79.2,31.3 ; C11.1 73.3,30.26 v1(73.5,30) ; 75.74,35.3 74.8,35.3 ; 77.97,31.3 77.33,31.3 v1(77,31.25) ; C16.1 76.74,35.3 v1(77,35.5) ; 78.26,34.3 79.2,34.3 ; 72.56,29 74.05,29 ; v1(77,34.5) 77.26,34.3 C15.1 ; 73.56,31 74.5,31
  BOTTOM w0.8: C11.1 73.56,31 ; C10.1 72.56,29 ; C16.1 75.74,35.3 ; C15.1 78.26,34.3 ; 78.26,31.3 C14.1 77.97,31.3
5V: length 80.4
  TOP w0.2: v1(94,22) 93.45,22.55 93.45,23.05 ; 93.4,45.9 PS1.A2 92.7,46.4 93.1,46.8 ; 93.3,42.63 93.3,44.7 93.45,44.85 93.45,45.1 PS1.C2 ; 93.45,56 PS2.B2 ; PS2.C2 93.45,55.6 93.45,55.35 93.3,55.2 93.3,53.13 ; 93.1,57.3 92.7,56.9 PS2.A2 93.45,56.4 ; PS1.B2 93.4,45.5
  TOP w0.25: CN3.4 46.75,6.4 v3(47,6.65) ; CN3.3 46.75,1.85 v3(47,2.1) 47.38,1.73 47.38,1.3
  TOP w0.3: 23.5,4.72 v1(23.5,5.75) 23.5,6.78 ; 25.5,4.72 v1(25.5,5.75) 25.5,6.78 ; 19.5,4.72 v1(19.5,5.75) 19.5,6.78 ; 21.5,6.78 v1(21.5,5.75) 21.5,4.72
  TOP w0.5: 39.95,12.81 39.95,13.75 39.71,13.99 IC7.20 ; 42,41.94 v1(42,41) ; IC6.20 39.71,23.99 39.95,23.75 39.95,22.81 ; IC15.3 93.45,23.05 ; IC15.4 93.45,25.9 93.65,26.1 94.77,26.1 ; CN3.2 48.5,5.22 ; CN3.2 47.38,6.8 ; CN3.2 v3(47.38,3) v3(47,2.1) ; 41.74,42.2 40.45,42.2 ; 18.47,51.45 v1(19.4,51.45) ; 18.47,54.95 v1(19.4,54.95) ; v2(96.5,26.1) 95.26,26.1 ; 96.8,60.24 96.8,58.26 v2(97,57.75) ; CN3.1 47.38,1.3 ; IC5.20 39.71,33.99 39.95,33.75 39.95,32.81
  TOP w0.6: C79.1 86.25,14.2 ; C79.1 88.7,14.2 ; C79.1 87.5,13 ; C92.1 96.7,56.3 ; C92.1 v2(95.5,57.75) ; C92.1 94.35,56.3 ; C81.1 94.4,45.8 ; C81.1 v2(95.5,47.25) ; C81.1 C82.1 v2(97,47.25) ; 39.64,32.75 v1(38.75,32.75) ; 39.64,22.75 v1(38.75,22.75) ; 39.64,12.75 v1(38.5,12.75)
  TOP w0.8: R80.1 25.5,4.72 ; 42,41.94 C57.1 41.74,42.2 ; R82.1 25.5,6.78 ; 94.77,26.1 C97.1 95.26,26.1 ; 96.8,60.24 R81.1 ; 39.64,22.75 C55.1 39.95,22.81 ; 93.3,53.13 C96.1 ; 39.95,12.81 C56.1 39.64,12.75 ; R78.1 23.5,4.72 ; 39.95,32.81 C54.1 39.64,32.75 ; 93.3,42.63 C85.1 ; R76.1 21.5,4.72 ; R75.1 19.5,6.78 ; R77.1 21.5,6.78 ; R79.1 23.5,6.78 ; R74.1 19.5,4.72
  TOP w0.9: D15.K 18.47,54.95 ; D16.K 18.47,51.45
  TOP w1: CN5.1 88.9,14
  BOTTOM w0.2: v2(96.5,26.1) 96.5,23.25 95.25,22 v1(94,22)
  BOTTOM w0.5: 15.7,56.24 15.7,54.95 ; 12.95,52.01 v1(12.95,53) ; 15.66,56.5 14.75,56.5 v1(14.5,56.25)
  BOTTOM w0.8: R86.1 12.95,52.01 ; 15.7,56.24 C78.1 15.66,56.5
  vias: v1(19.35,59) v1(19.35,58) v1(19.35,57) v2(86,14) v2(86,12.5) v2(86,11) v3(48.1,6.65) v3(48.4,5.5) v3(49.2,6.65) v3(49.4,5.5)
GND: length 1090.4
  TOP w0.15: 18.99,11.16 18.99,10.64 18.85,10.5 v1(18,10.5) ; v1(45.5,33) 45.5,33.85 45.36,33.99 44.84,33.99 ; 45.7,29.27 44.92,29.27 ; 45.7,29.27 45.7,29.81 45.5,30.01 44.93,30.01 ; 45.7,29.27 45.7,28.8 45.52,28.62 44.92,28.62 ; 19.73,17.93 v1(19.73,18.9) ; 45.7,39.27 45.7,39.81 45.5,40.01 44.93,40.01 ; 45.7,39.27 45.7,38.8 45.52,38.62 44.92,38.62 ; 45.7,39.27 44.92,39.27 ; 44.84,13.99 45.31,13.99 45.5,13.8 v1(45.5,13) ; 38.08,34.73 37.73,34.73 v1(36.5,33.5) ; v1(45.5,23) 45.5,23.85 45.36,23.99 44.84,23.99 ; v1(36.5,23.5) 37.73,24.73 38.08,24.73 ; v1(36.5,14) 37.23,14.72 38.08,14.72
  TOP w0.2: v1(91.3,44.6) 91.8,45.1 PS1.C1 v1(92.3,44) ; v1(92.3,54.5) PS2.C1 91.8,55.6 v1(91.3,55.1) ; v1(50.75,64) 50.64,64.31 50.2,64.75 46.55,64.75 46.3,64.5 ; v1(64.25,57.65) 63.97,57.48 63.36,57.48 ; 60.62,57.48 63.14,57.48 ; v1(40.75,46) 40.64,46.31 40.2,46.75 38.8,46.75 38.36,46.31 v1(38.25,46)
  TOP w0.25: 71.45,26.26 71.45,27.15 71.75,27.45 IC3.34 ; v1(67.5,7) 67.24,6.8 56.2,6.8 51.8,11.2 45.55,11.2 42.75,8.4 CN3.20 v3(42.75,3.9) ; IC3.32 70.75,29.75 v1(70.5,30) ; IC3.50 77.25,32.75 v1(77,32.5) ; 70.7,4.7 79.7,4.7 v1(82,7) ; 70.7,4.7 55.1,4.7 50.6,9.2 46.15,9.2 44.75,7.8 CN3.12 v3(44.75,3.9) ; 70.7,4.7 v1(73,7) ; v1(69.75,7) 68.45,5.7 55.7,5.7 51.2,10.2 45.85,10.2 43.75,8.1 CN3.16 v3(43.75,3.9) ; v1(71.5,30) 71.25,29.75 IC3.33 ; CN3.15 v3(43.75,2.1) ; CN3.11 v3(44.75,2.1) ; 42.1,9.3 41.75,8.95 CN3.24 v3(41.75,3.9) ; v3(39.75,3.9) CN3.32 v3(39.75,6.5) ; 32.62,5.79 v3(32.62,6.5) ; CN3.31 v3(39.75,2.1) ; v1(77,33.5) 77.25,33.25 IC3.51 ; 32.62,1.44 v3(32.62,2.1) ; CN3.7 45.75,1.85 v3(46,2.1) 46.25,1.85 CN3.5 ; v1(60.5,55) 60.25,54.75 IC3.122 ; CN3.23 v3(41.75,2.1) ; CN3.50 v3(35.25,6.5) ; CN3.19 v3(42.75,2.1) ; v3(37.75,6.5) CN3.40 v3(37.75,3.9) ; IC3.52 79.55,33.75 79.85,33.45 80.74,33.45 ; CN3.39 v3(37.75,2.1) ; CN3.8 45.75,4.15 v3(46,3.9) 46.25,4.15 CN3.6 46.25,6.25 v3(46,6.5) 45.75,6.25 CN3.8
  TOP w0.3: 46.75,59.53 v1(46.75,58.5) ; 48.47,16.25 v1(49.5,16.25) 50.53,16.25 ; X1.2 59.7,59.55 ; X1.2 58.8,58.5 ; X1.2 60.6,58.5 ; X1.2 59.7,57.55 ; 48.47,25.75 v1(49.5,25.75) ; 77.5,24.53 v1(77.5,23.5) ; 50.53,18.25 v1(49.5,18.25) 48.47,18.25 ; 48.47,32.75 v1(49.5,32.75) ; v1(84.5,39.5) 84.5,38.47 ; 42.35,59.87 41.49,59.87 ; 42.35,59.87 42.35,61.13 ; 42.35,59.87 42.35,59.06 v1(42.25,58.75) ; 52.38,58.5 v1(53.15,58.5) ; 48.47,20.25 v1(49.5,20.25) 50.53,20.25 ; 48.47,34.25 v1(49.5,34.25) ; 42.35,61.13 41.49,61.13 ; 42.35,61.13 42.35,61.94 v1(42.25,62.25) ; 48.47,24.25 v1(49.5,24.25) ; 60.12,14.5 v1(61.85,14.5) ; 48.47,27.25 v1(49.5,27.25) ; 48.47,28.75 v1(49.5,28.75) ; 67,22.78 v1(67,21.75) ; 59.97,63.75 v1(61,63.75) ; v2(94.25,33.75) C83.2 92.97,34.45 93.4,34.88 ; 48.47,40.25 v1(49.5,40.25) ; 84.5,33.28 v1(84.5,32.25) ; C64.2 v1(83.4,31) ; 74.5,22.78 v1(74.5,21.75) ; 48.47,22.75 v1(49.5,22.75) ; 48.47,37.25 v1(49.5,37.25) ; 48.47,30.25 v1(49.5,30.25) ; 48.47,35.75 v1(49.5,35.75) ; 59.97,62.25 v1(61,62.25) ; 50.53,14.25 v1(49.5,14.25) 48.47,14.25 ; 80.5,24.53 v1(80.5,23.5) ; 59.97,60.75 v1(61,60.75) ; 70,22.78 v1(70,21.75) ; v1(84.75,7) 80.75,3 ; 48.47,38.75 v1(49.5,38.75) ; 41.6,66.35 41.85,66.1 v1(45,66.1) 61.55,66.1 v1(61.85,65.8) ; 74.62,14.5 v1(76.35,14.5) ; 65.25,57.97 v1(65.25,59)
  TOP w0.35: 44.92,28.62 IC6.8 ; 38.08,14.72 IC7.19 ; 44.92,38.62 IC5.8 ; IC6.19 38.08,24.73 ; IC11.19 19.73,17.93 ; 44.92,39.27 IC5.9 ; IC5.19 38.08,34.73 ; IC9.11 74.62,14.5 ; IC10.11 60.12,14.5 ; 44.92,29.27 IC6.9
  TOP w0.45: 63.14,57.48 C6.2 63.36,57.48 ; C17.2 52.38,58.5
  TOP w0.5: v2(94.75,32.25) C90.2 C84.2 v2(94.75,30.75) ; v1(61.85,11.75) 61.7,11.46 C69.2 ; TP13.1 96,30.1 ; TP13.1 93.95,28.5 ; TP13.1 v1(98.25,28.5) ; 92.5,21.76 IC15.2 92.5,24.25 ; TP24.1 89,64.65 ; TP24.1 87,63 v1(87,62) ; TP24.1 91,63 ; TP24.1 89,61.35 ; 41.97,43.8 41.05,43.8 v1(40.75,43.5) v1(38.55,43.5) IC8.3 ; 27.83,59.37 28.59,59.37 C77.2 ; 18.47,49.55 v1(19.4,49.55) ; CN3.59 32.62,1.44 ; v1(80.5,7.75) 81.25,8.5 83,8.5 84.6,10.1 84.6,21.35 87,23.75 87,24.75 86.75,25 86.75,30.75 v1(87,31) 87.75,31.75 87.75,38.25 86.5,39.5 v1(84.5,39.5) ; TP25.1 5,64.6 ; TP25.1 7,63 ; TP25.1 v1(5,60.5) ; TP25.1 3,63 ; 72.53,62.45 v1(71.5,62.45) ; 97.06,62 v1(98.25,62) ; IC7.10 v1(41.55,20.01) ; 77.53,65.95 v1(76.5,65.95) ; v1(42.75,40.01) IC5.10 44.93,40.01 ; IC5.1 44.84,33.99 ; 72.53,65.95 v1(71.5,65.95) ; 92.25,24.5 90.26,24.5 ; 92.25,24.5 92.5,24.5 ; 92.25,24.5 92.5,24.25 ; v1(61.45,21.25) 61.45,21.95 62,22.5 63.75,22.5 64.35,23.1 64.35,25.1 64.85,25.6 65.85,25.6 66.5,26.25 v1(66.5,27) ; IC6.1 44.84,23.99 ; v1(41.55,30.01) IC6.10 44.93,30.01 ; 23.47,25.05 v1(24.4,25.05) ; 18.47,33.05 v1(19.4,33.05) ; v1(76.35,11.75) 76.2,11.46 C60.2 ; 18.47,53.05 v1(19.4,53.05) ; TP14.1 23,46.15 ; TP14.1 v1(21,44.5) ; TP14.1 23,42.8 ; 92.5,24.5 92.75,24.5 ; 92.5,24.5 92.5,24.25 ; v3(46,3.9) v3(46.25,3) v3(46,2.1) ; 23.47,29.05 v1(24.4,29.05) ; 92.5,21.24 v2(92.5,20) ; 18.47,25.05 v1(19.4,25.05) ; 23.47,37.05 v1(24.4,37.05) ; 42.1,9.3 45.2,12.4 53.35,12.4 57.75,8 v1(58.75,8) ; 44,63.47 v1(44,64.4) ; 92.5,24.25 92.75,24.5 ; 18.47,29.05 v1(19.4,29.05) ; 55.22,63.91 v1(54,63.91) ; 91.7,42.76 91.7,43.55 ; 18.47,37.05 v1(19.4,37.05) ; IC7.1 44.84,13.99 ; 67.53,62.45 v1(66.5,62.45) ; 52.31,57.25 v1(53.15,57.25) ; 94.74,24.5 92.75,24.5 ; 91.7,53.26 91.7,54.05 ; IC11.10 v1(25.01,13.5) ; v3(46,6.5) v3(46,7.5) 46.5,8 50,8 54.75,3.25 ; IC11.1 18.99,11.16 ; CN3.60 32.62,5.79 ; 18,64.73 v1(18,63.5) ; 10.2,22 v1(11.5,22) ; 90.9,44.2 v1(91.3,44.6) ; 67.53,65.95 v1(66.5,65.95) ; 23.47,33.05 v1(24.4,33.05) ; 29,58.94 v1(29,58) ; 52.31,55.75 v1(53.15,55.75) ; 10.2,50 v1(11.5,50)
  TOP w0.6: 75.44,57.8 v1(74.75,57.8) ; 71.45,24.44 v1(71.45,23.75) ; C79.2 88.7,15.8 ; C79.2 v2(87.5,17.5) ; C79.2 86.3,15.8 ; 54.39,26.25 v1(53.5,26.25) ; 72.06,57.8 v1(72.75,57.8) ; 82.3,51.19 v1(82.3,50.5) ; C82.2 C81.2 ; C82.2 v2(97,42.75) ; C82.2 98.2,44.2 ; C81.2 94.25,44.2 ; C81.2 v2(95.5,42.75) ; C93.2 C94.2 ; C93.2 90.9,54.7 v1(91.3,55.1) ; C93.2 v2(89.5,53.25) ; C94.2 86.8,54.7 ; C94.2 v2(88,53.25) ; 82.3,48.44 v1(82.3,47.75) ; 82.3,45.56 v1(82.3,46.25) ; C87.2 C88.2 ; C87.2 C86.2 ; C87.2 v2(88,42.75) ; C88.2 v2(86.5,42.75) ; C88.2 C89.2 ; 27.83,59.37 IC12.2 ; C92.2 96.7,54.7 ; C92.2 v2(95.5,53.25) ; C92.2 94.3,54.7 ; C89.2 83.8,44.2 ; C89.2 v2(85,42.75) ; 81.06,33.45 81.94,33.45 ; C86.2 90.9,44.2 ; C86.2 v2(89.5,42.75) ; 82.56,33.45 v1(83.25,33.45) ; 17.81,14.45 v1(18.75,14.45) ; 41.55,33.06 v1(41.55,33.75) ; 68.56,57.8 v1(69.25,57.8) ; 82.3,39.06 v1(82.3,39.75) ; 41.55,13.06 v1(41.55,13.75) ; 57.19,57.8 v1(56.5,57.8) ; 82.3,43.44 v1(82.3,42.75) ; IC4.4 55.22,63.91 ; 71.45,25.94 71.45,25.06 ; 41.55,23.06 v1(41.55,23.75) ; C49.2 v1(49.2,50.25) ; 82.3,41.44 v1(82.3,40.75) ; C50.2 v1(49.2,45.75)
  TOP w0.7: 92.5,21.76 92.5,21.24 ; 41.49,61.13 SW2.2 ; 41.49,59.87 SW2.1
  TOP w0.8: C43.2 68.56,57.8 ; C74.2 67,22.78 ; R42.2 50.53,14.25 ; R19.1 65.25,57.97 ; C39.2 82.3,48.44 ; R46.2 50.53,18.25 ; C73.2 84.5,33.28 ; R31.2 48.47,34.25 ; R32.2 48.47,35.75 ; C72.2 70,22.78 ; C66.2 80.5,24.53 ; R41.2 48.47,30.25 ; C48.2 57.19,57.8 ; R25.1 46.75,59.53 ; R49.2 48.47,20.25 ; R22.1 59.97,60.75 ; C96.2 91.7,53.26 ; R34.2 48.47,38.75 ; C18.2 52.31,57.25 ; R36.2 48.47,22.75 ; C91.2 90.26,24.5 ; R40.2 48.47,28.75 ; C35.2 82.3,39.06 ; C76.2 17.81,14.45 ; 82.56,33.45 C13.2 81.94,33.45 ; C56.2 41.55,13.06 ; C40.2 82.3,51.19 ; R37.2 48.47,24.25 ; C77.2 29,58.94 ; R44.2 50.53,16.25 ; C65.2 74.5,22.78 ; R33.2 48.47,37.25 ; C85.2 91.7,42.76 ; C37.2 82.3,43.44 ; 81.06,33.45 C12.2 80.74,33.45 ; C54.2 41.55,33.06 ; 71.45,24.44 C9.2 71.45,25.06 ; 84.5,38.47 C75.2 ; C30.2 54.39,26.25 ; C38.2 82.3,45.56 ; C42.2 72.06,57.8 ; 71.45,25.94 C8.2 71.45,26.26 ; C57.2 41.97,43.8 ; R45.2 48.47,16.25 ; R48.2 50.53,20.25 ; R39.2 48.47,27.25 ; C41.2 75.44,57.8 ; R23.1 59.97,62.25 ; R35.2 48.47,40.25 ; R43.2 48.47,14.25 ; C19.2 52.31,55.75 ; 94.74,24.5 C97.2 ; C55.2 41.55,23.06 ; R24.1 59.97,63.75 ; R38.2 48.47,25.75 ; C63.2 77.5,24.53 ; LED1.K 97.06,62 ; R47.2 48.47,18.25 ; R30.2 48.47,32.75 ; C36.2 82.3,41.44
  TOP w0.9: D2.A 67.53,65.95 ; D16.A 18.47,49.55 ; D18.A 23.47,37.05 ; D23.A 18.47,25.05 ; D20.A 23.47,33.05 ; D15.A 18.47,53.05 ; D22.A 23.47,29.05 ; D5.A 77.53,65.95 ; D1.A 67.53,62.45 ; D4.A 72.53,65.95 ; D19.A 18.47,33.05 ; D24.A 23.47,25.05 ; D17.A 18.47,37.05 ; D3.A 72.53,62.45 ; D21.A 18.47,29.05
  TOP w1: CN4.3 18,64.73 ; CN7.10 10.2,22 ; SW1.1 44,63.47 ; CN6.4 10.2,50 ; v1(93.5,16) CN5.2 88.9,16
  BOTTOM w0.15: 60.6,26.1 60.9,26.4 63.1,26.4 ; v3(42.75,2.1) v3(42.75,3.9) ; v3(43.75,2.1) v3(43.75,3.9) ; 32,60.5 32.5,60 32.5,52.5 32.6,52.4 32.6,51 32.3,50.7 ; v3(41.75,2.1) v3(41.75,3.9) ; v3(39.75,3.9) v3(39.75,2.1) ; v3(44.75,2.1) v3(44.75,3.9) ; v3(37.75,3.9) v3(37.75,2.1)
  BOTTOM w0.2: v1(36.5,14) 36.7,13.74 36.7,11.3 37,11 37,7.25 v3(37.75,6.5) ; v1(77.1,52.1) 76.5,52.7 76.5,62.25 v1(77,62.75)
  BOTTOM w0.25: 66.2,5.7 v1(67.5,7) 68.35,7.85 68.35,15.65 v1(67.5,16.5) ; 66.2,5.7 55.5,5.7 51,10.2 45.85,10.2 44.1,8.45 44.1,5.35 43.75,5 v3(43.75,3.9) ; 66.2,5.7 68.95,5.7 69.75,6.5 v1(69.75,7) ; v1(82,16.5) 82.85,15.65 82.85,7.55 82.3,7 v1(82,7) ; 71.15,4.7 71.15,5.9 ; 71.15,4.7 77.45,4.7 v1(80.5,7.75) ; 71.15,4.7 69.95,4.7 ; 71.15,5.9 71.15,15.65 v1(72,16.5) ; 71.15,5.9 69.95,4.7 ; v3(42.75,3.9) 42.75,5.5 43.2,5.95 43.2,8.85 45.55,11.2 51.8,11.2 ; 69.95,4.7 54.9,4.7 50.4,9.2 46.15,9.2 45,8.05 45,4.75 44.75,4.5 v3(44.75,3.9) ; IC2.2 v1(39.5,54) 40.3,53.2 40.3,52.28 ; 35.39,53.75 v1(34.5,53.75) ; 43.3,54.4 43.3,55.6 ; v1(57.5,16.5) 57,16 57,13 55.2,11.2 51.8,11.2 ; 42.6,9.8 42.3,9.5 42.3,6.55 41.75,6 v3(41.75,3.9) ; 38.39,58.5 v1(37.7,58.5) ; IC1.2 v1(42.5,57.5) 43.3,56.7 43.3,55.78 ; 51.8,11.2 56.2,6.8 65.05,6.8 v1(66,7.75) ; 40.3,50.9 40.3,52.1 ; 35.39,54.75 v1(34.5,54.75)
  BOTTOM w0.3: 40.93,67.45 CN2.3 39.65,67.3 ; 50.9,67.64 CN2.11 49.81,67.2 ; 72.1,73.45 CN1.4 69.7,73.49 ; v1(77.1,52.1) 78.8,50.4 78.8,47 ; v1(32.75,9.5) 32.75,9 v3(35.25,6.5) ; 60.86,13.75 61.85,13.75 v1(61.85,13) 61.85,12.25 60.86,12.25 ; 75.36,15.25 76.35,15.25 v1(76.35,16) 76.35,16.3 75.9,16.75 R57.2 ; 77.31,73.5 CN1.10 79.8,73.53 ; 78.64,16.75 77.65,16.75 v1(77.65,16) 77.65,15.45 77.85,15.25 C61.2 ; 75.36,13.75 76.35,13.75 v1(76.35,13) 76.35,12.25 75.36,12.25 ; v1(77.65,17.25) 78.05,17.65 D9.A ; 78.05,8.62 v1(78.05,7.75) ; 37.7,57.42 v1(37.7,58.5) ; 40.96,67.5 CN2.5 43.42,67.5 ; 68.45,25.8 68.45,26.75 68.9,27.2 69.95,27.2 70.1,27.35 85,27.35 ; R69.2 61.4,16.75 61.85,16.3 v1(61.85,16) 61.85,15.25 60.86,15.25 ; v1(51.75,43.5) v1(40.75,43.5) v1(38.55,43.5) 33.5,43.5 v1(27.9,37.9) 25.4,35.4 ; v1(63.15,17.25) 63.55,17.65 D13.A ; C70.2 63.35,15.25 63.15,15.45 v1(63.15,16) 63.15,16.75 64.14,16.75 ; 33.75,52.85 33.75,51.5 ; 74.75,73.52 CN1.8 77.25,73.52 ; R64.2 63.6,12.25 63.15,12.7 v1(63.15,13) 63.15,13.55 63.35,13.75 C67.2 ; D12.A 61.45,11.35 v1(61.85,11.75) ; 46,67.46 CN2.7 43.5,67.5 ; v1(76.35,11.75) 75.95,11.35 D8.A ; CN2.9 46.04,67.5 ; 67.6,63.88 67.6,64.85 v1(66.5,65.95) ; 79.85,73.5 CN1.12 82.11,73.3 ; 61.45,20.38 v1(61.45,21.25) ; 75.95,20.38 v1(75.95,21.25) ; R52.2 78.1,12.25 77.65,12.7 v1(77.65,13) 77.65,13.55 77.85,13.75 C58.2 ; 63.55,8.62 v1(63.55,7.75)
  BOTTOM w0.45: C5.2 35.39,53.75 ; C7.2 38.39,58.5 ; C1.2 35.39,54.75
  BOTTOM w0.5: v1(64.25,52) 64.3,51.67 64.3,51.03 ; v1(77,33.5) 76.74,33.7 C16.2 ; 35.5,33.5 35.5,23.75 35.75,23.5 v1(36.5,23.5) v1(36.5,20.5) v1(36.5,14) ; 35.5,33.5 35.5,40 35.85,40.35 37.15,40.35 41.55,35.95 v1(41.55,33.75) 44.75,33.75 v1(45.5,33) v1(45.5,23) v1(45.5,13) ; 35.5,33.5 v1(36.5,33.5) 36.5,31.75 38.24,30.01 v1(41.55,30.01) v1(41.55,23.75) v1(41.55,20.01) v1(41.55,13.75) ; IC14.3 v1(17,47.95) v1(17,45.75) 16.7,45.45 16.7,44.53 ; 55.97,48.2 55.33,48.2 v1(55,48.25) ; 69.75,16.5 v1(69.75,7) ; 69.75,16.5 68.75,17.5 68.75,19.75 68,20.5 65.75,20.5 v1(65,21.25) ; 69.75,16.5 70.75,17.5 70.75,19.75 71.5,20.5 74.25,20.5 75,21.25 v1(75.95,21.25) ; v1(77,32.5) 77.26,32.7 C15.2 ; 42.6,9.8 45.2,12.4 54.15,12.4 55.5,13.75 55.5,16.75 56.25,17.5 56.25,19.75 57,20.5 59.75,20.5 60.5,21.25 v1(61.45,21.25) ; v1(56.75,55) 56.7,54.67 56.7,54.03 ; 66.15,51.1 66.5,50.75 v1(67.5,50.75) v1(69,50.75) ; 66.8,30.96 66.8,30.33 v1(66.75,30) ; C31.2 58.7,27.3 v1(58.4,27) ; v3(37.75,6.5) v3(37.75,3.9) ; C51.2 52.05,43.8 v1(51.75,43.5) ; v1(70.5,30) 70.7,29.74 C10.2 ; v1(71.5,30) 71.7,30.26 C11.2 ; v1(65.75,55) 65.8,54.67 65.8,54.03 ; v1(77,44.25) 76.67,44.2 76.03,44.2 ; v3(39.75,6.5) v3(39.75,3.9) ; v1(55,37.75) 55.33,37.7 55.97,37.7 ; 54.75,3 49.75,8 46.5,8 v3(46,7.5) v3(46,6.5) v3(46,3.9) ; 76.03,39.8 76.67,39.8 v1(77,39.75) ; 55.97,43.3 55.33,43.3 v1(55,43.25) ; v1(61.25,30) 61.2,30.33 61.2,30.96 ; v1(84.75,7) 84.68,7.32 84.25,7.75 84.25,16.5 83.25,17.5 83.25,19.75 82.5,20.5 80.25,20.5 v1(79.5,21.25) ; 69.3,28.26 v1(69.3,30) ; 17.3,56.47 17.3,55.55 v1(17,55.25) v1(17,53.05) D15.A ; v1(60.5,55) 60.2,54.7 C46.2 ; v1(63.25,27) 63.3,27.33 63.3,27.96 ; v1(55,32.25) 55.33,32.2 55.97,32.2 ; 63.25,58.06 v1(63.25,59) ; v1(82,7) 78.25,3.25 ; C53.2 52.05,32.7 v1(51.75,33) ; C25.2 60.05,51.74 v1(60.25,52) ; C33.2 66.3,27.26 v1(66.5,27) ; 77.97,29.7 77.33,29.7 v1(77,29.75) ; v1(51.75,37.25) 52.08,37.2 52.72,37.2
  BOTTOM w0.8: R4.2 40.3,50.9 ; C22.2 76.03,39.8 ; C68.2 60.86,13.75 ; C71.2 60.86,15.25 ; C14.2 77.97,29.7 ; 67.6,63.88 R14.2 ; C21.2 66.8,30.96 ; C52.2 52.72,37.2 ; C47.2 56.7,54.03 ; C44.2 65.8,54.03 ; R56.2 78.64,16.75 ; 40.3,52.1 C4.2 40.3,52.28 ; C28.2 55.97,37.7 ; R3.2 43.3,54.4 ; C24.2 64.3,51.03 ; C62.2 75.36,15.25 ; C32.2 63.3,27.96 ; 43.3,55.78 C2.2 43.3,55.6 ; C34.2 69.3,28.26 ; R65.2 60.86,12.25 ; C78.2 17.3,56.47 ; R68.2 64.14,16.75 ; C26.2 55.97,48.2 ; C3.2 37.7,57.42 ; C59.2 75.36,13.75 ; C80.2 16.7,44.53 ; C29.2 55.97,32.2 ; C23.2 76.03,44.2 ; C45.2 63.25,58.06 ; C20.2 61.2,30.96 ; R53.2 75.36,12.25 ; C27.2 55.97,43.3
  BOTTOM w0.9: D14.A 61.45,20.38 ; D10.A 75.95,20.38 ; D11.A 63.55,8.62 ; D7.A 78.05,8.62
  vias: v1(1.75,62) v1(1.75,55) v1(1.75,48) v1(1.75,41) v1(1.75,34) v1(1.75,27) v1(1.75,20) v1(1.75,13) v1(6.5,53) v1(6.5,37) v1(6.5,31) v1(6.5,25) v1(7.25,62) v1(7.25,13) v1(7.5,58) v1(7.5,48) v1(7.5,42) v1(7.5,20) v1(13,72.5) v1(13,67.5) v1(13,62) v1(13,13) v1(13,7.5) v1(13,2.5) v1(13.5,50) v1(13.55,55.2) v1(14.5,73.25) v1(14.5,1.75) v1(15.5,44.5) v1(15.75,49.25) v1(18,5.75) v1(19.5,47) v1(20,73.25) v1(20.75,55.5) v1(20.75,41.5) v1(21.5,15.5) v1(21.5,13.5) v1(22.25,52.75) v1(23,49) v1(24,46.25) v1(24,42.75) v1(25,15.5) v1(25.5,73.25) v1(25.75,18.75) v1(26.75,5.75) v1(27,2) v1(27.5,63.25) v1(28,42.8) v1(28,32.8) v1(28,27.85) v1(28,22.85) v1(28.25,1.75) v1(28.75,9.75) v1(29,51.75) v1(29.75,55.75) v1(30,17.8) v1(30.75,37.2) v1(31.5,73.25) v1(32.25,37.2) v1(32.5,32.8) v1(32.5,28.1) v1(32.5,22.85) v1(32.75,66.5) v1(34.5,58.5) v1(35.25,70) v1(35.25,67.25) v1(35.25,48.75) v1(37,63) v1(38.25,73.25) v1(39.75,41) v1(40.5,27) v1(40.75,66.75) v1(42.75,49.25) v1(44.75,47) v1(46.25,51.25) v1(47.75,53.5) v1(48,59) v1(51,54.5) v1(51.5,22) v1(52,50.5) v1(52,3) v1(52.5,61.8) v1(53,29) v1(53.5,73.25) v1(54,60) v1(54,28.25) v1(55,47) v1(55,44.5) v1(55,40.5) v1(55,36.5) v1(55,35) v1(55,30) v1(55.35,55.9) v1(56,22) v1(57,68.5) v1(57,51.5) v1(57,47) v1(57,44) v1(57,36.5) v1(57,35) v1(57,30) v1(57,3) v1(57.2,49.8) v1(57.2,48.5) v1(57.2,42.5) v1(57.2,41) v1(57.2,39.5) v1(57.2,38) v1(57.2,33.5) v1(57.2,32) v1(57.5,11) v1(58.5,49.8) v1(58.5,48.5) v1(58.5,44) v1(58.5,42.5) v1(58.5,41) v1(58.5,39.5) v1(58.5,38) v1(58.5,36.5) v1(58.5,35) v1(58.5,33.5) v1(58.5,32) v1(58.5,30) v1(59.15,55.35) v1(60,49.8) v1(60,45.5) v1(60,44) v1(60,42.5) v1(60,41) v1(60,39.5) v1(60,38) v1(60,36.5) v1(60,35) v1(60,33.5) v1(60,32) v1(60,30) v1(60.25,7.75) v1(60.5,73.25) v1(61,23.5) v1(61.5,52) v1(61.5,47) v1(61.5,45.5) v1(61.5,44) v1(61.5,42.5) v1(61.5,41) v1(61.5,39.5) v1(61.5,38) v1(61.5,36.5) v1(61.5,35) v1(61.5,33.5) v1(61.5,32.2) v1(61.75,68.5) v1(62,3) v1(62.5,19.25) v1(63,48.5) v1(63,47) v1(63,45.5) v1(63,44) v1(63,42.5) v1(63,41) v1(63,39.5) v1(63,38) v1(63,36.5) v1(63,35) v1(63,33.5) v1(63,32.2) v1(64,30) v1(64.5,48.5) v1(64.5,47) v1(64.5,45.5) v1(64.5,44) v1(64.5,42.5) v1(64.5,41) v1(64.5,39.5) v1(64.5,38) v1(64.5,36.5) v1(64.5,35) v1(64.5,33.5) v1(64.5,32.2) v1(65.75,52) v1(66,48.5) v1(66,47) v1(66,45.5) v1(66,44) v1(66,42.5) v1(66,41) v1(66,39.5) v1(66,38) v1(66,36.5) v1(66,35) v1(66,33.5) v1(66,32.2) v1(66.5,73.25) v1(67,3) v1(67.5,48.5) v1(67.5,47) v1(67.5,45.5) v1(67.5,44) v1(67.5,42.5) v1(67.5,41) v1(67.5,39.5) v1(67.5,38) v1(67.5,36.5) v1(67.5,35) v1(67.5,33.5) v1(67.5,32.2) v1(67.5,11) v1(68,30) v1(69,48.5) v1(69,47) v1(69,45.5) v1(69,44) v1(69,42.5) v1(69,41) v1(69,39.5) v1(69,38) v1(69,36.5) v1(69,35) v1(69,33.5) v1(69,32) v1(69.25,55) v1(70.2,62.6) v1(70.5,48.5) v1(70.5,47) v1(70.5,45.5) v1(70.5,44) v1(70.5,42.5) v1(70.5,41) v1(70.5,39.5) v1(70.5,38) v1(70.5,36.5) v1(70.5,35) v1(70.5,33.5) v1(70.5,32) v1(71.25,68) v1(72,49.75) v1(72,48.5) v1(72,47) v1(72,45.5) v1(72,44) v1(72,42.5) v1(72,41) v1(72,39.5) v1(72,38) v1(72,36.5) v1(72,35) v1(72,33.5) v1(72,32.2) v1(72,11) v1(72,3) v1(72.75,55) v1(73.25,8.45) v1(73.3,36.5) v1(73.3,35) v1(73.3,33.5) v1(73.3,32.2) v1(73.5,49.75) v1(73.5,48.5) v1(73.5,47) v1(73.5,45.5) v1(73.5,44) v1(73.5,42.5) v1(73.5,41) v1(73.5,39.5) v1(73.5,38) v1(74.75,68) v1(74.75,55) v1(74.8,48.5) v1(74.8,47) v1(74.8,45.5) v1(74.8,44) v1(74.8,39.5) v1(74.8,38) v1(74.75,7.75) v1(75,42.5) v1(75,41) v1(75.2,62.6) v1(75.25,50.25) v1(77,42.5) v1(77,41) v1(77,19.25) v1(77,3) v1(77.25,68) v1(78,61) v1(78.75,58.25) v1(79.75,68) v1(80.25,62.5) v1(80.4,37.6) v1(82,11) v1(82,3) v1(82.25,68) v1(83,54.5) v1(84.75,22.5) v1(85.5,73.25) v1(87,72.5) v1(87,67.5) v1(87,8.75) v1(87,3) v1(89.5,49.5) v1(90,23) v1(91.5,27.5) v1(92.5,49.5) v1(93.75,37.75) v1(94,59.8) v1(94,27.5) v1(95,23) v1(98.25,55) v1(98.25,48.3) v1(98.25,41) v1(98.25,34) v1(98.25,27) v1(98.25,20) v1(98.25,13) v2(86,17.5) v2(86,16) v3(31.5,5.25)
